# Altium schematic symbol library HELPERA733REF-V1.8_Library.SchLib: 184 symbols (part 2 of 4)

## AO4409_5
designator U?
pins: 1 PK14/MCSIB-CKN/PCIE-PERSTN/PWM0-7/NCSI1-D5/PK-EINT14, 2 PK15/MCSIB-CKP/PWM0-8/NCSI1-D4/PK-EINT15, 3 PK16/MCSIB-D2N/TWI3-SCK/UART2-TX/PWM0-9/NCSI1-D3/PK-EINT16, 4 PK17/MCSIB-D2P/TWI3-SDA/UART2-RX/PWM1-0/NCSI1-D2/PK-EINT17, 5 PK18/MCSIB-D3N/MCSI1-MCLK/UART2-RTS/PWM1-1/NCSI1-D1/TWI9-SCK/PK-EINT18, 6 PK19/MCSIB-D3P/MCSI2-MCLK/UART2-CTS/PWM1-2/NCSI1-D0/TWI9-SDA/PK-EINT19, 7 PE3/TWI3-SCK/CSI1-XVS-FSYNC/PWM0-0/SPI3-MISO/LPC-LFRAME/NCSI0-D1/UART6-CTS/PE-EINT3, 8 PE4/TWI3-SDA/LEDC/PWM0-1/SPI3-CS1/LPC-LSMI/NCSI0-D0/UART6-DCD/PE-EINT4, 9 PE5/MCSI1-MCLK/PLL-LOCK-DBG/PWM0-2/LPC-LCLK/NCSI0-MCLK/UART6-DSR/PE-EINT5, 10 PK8/MCSIA-D3N/MCSI0-MCLK/UART4-RTS/UART2-TX/SPI3-CS1/NCSI1-D11/JTAG-MAS-NTRST/PK-EINT8, 11 PK9/MCSIA-D3P/MCSI2-MCLK/UART4-CTS/UART2-RX/NCSI1-D10/JTAG-MAS-SRST/PK-EINT9, 12 PK6/MCSIA-D2N/TWI2-SCK/UART4-TX/UART2-RTS/SPI3-MOSI/NCSI1-D13/JTAG-MAS-DO/PK-EINT6, 13 PK7/MCSIA-D2P/TWI2-SDA/UART4-RX/UART2-CTS/SPI3-MISO/NCSI1-D12/JTAG-MAS-DI/PK-EINT7, 14 PK2/MCSIA-D1N/UART6-DTR/I2S4-LRCK/HDMI-SDA/TWI5-SDA/NCSI1-PCLK/SGPIO-SDATAIN/PK-EINT2, 15 PK3/MCSIA-D1P/UART6-RI/I2S4-DIN0/I2S4-DOUT1/TWI5-SCK/NCSI1-MCLK/SGPIO-SDATAOUT/PK-EINT3, 16 PK0/MCSIA-D0N/UART6-DCD/I2S4-BCLK/HDMI-CEC/TWI1-SDA/NCSI1-HSYNC/SGPIO-SLOAD/PK-EINT0, 17 PK1/MCSIA-D0P/UART6-DSR/I2S4-MCLK/HDMI-SCL/TWI1-SCK/NCSI1-VSYNC/SGPIO-SCLK/PK-EINT1, 18 PK4/MCSIA-CKN/PCIE-WAKEN/I2S4-DOUT0/I2S4-DIN1/SPI3-CS0/NCSI1-D15/JTAG-MAS-MS/PK-EINT4, 19 PK5/MCSIA-CKP/PCIE-CLKREQN/PWM1-8/PWM1-9/SPI3-CLK/NCSI1-D14/JTAG-MAS-CK/PK-EINT5, 20 PK22/MCSIC-D1N/TWI3-SCK/UART3-RTS/PWM1-6/NCSI1-HSYNC/UART1-TX/PK-EINT22, 21 PK23/MCSIC-D1P/TWI3-SDA/UART3-CTS/PWM1-7/NCSI1-VSYNC/UART1-RX/PK-EINT23, 22 PK20/MCSIC-D0N/TWI2-SCK/UART3-TX/PWM0-1/NCSI1-PCLK/UART1-RTS/PK-EINT20, 23 PK21/MCSIC-D0P/TWI2-SDA/UART3-RX/PWM0-2/NCSI1-MCLK/UART1-CTS/PK-EINT21, 24 PK24/MCSIC-CKN/MCSI0-MCLK/PWM0-6/TWI12-SCK/TWI10-SDA/PK-EINT24, 25 PK25/MCSIC-CKP/MCSI1-MCLK/PWM0-7/TWI12-SDA/TWI10-SCK/PK-EINT25, 26 PE0/MCSI0-MCLK/CSI0-XHS/SPI3-CS0/LPC-LAD0/NCSI0-HSYNC/UART6-TX/PE-EINT0, 27 PE9/MCSI2-MCLK/TCON-FSYNC0/I2S3-MCLK/LPC-LRESET/NCSI0-D5/UART6-RI/PE-EINT9, 28 PE6/CLK-FANOUT1/HDMI-CEC/I2S3-DIN0/I2S3-DOUT1/LPC-SERIRQ/NCSI0-D2/UART6-DTR/PE-EINT6, 29 PE7/CLK-FANOUT2/HDMI-SCL/I2S3-BCLK/LPC-LAD1/NCSI0-D3/TWI11-SCK/PE-EINT7, 30 PE8/CLK-FANOUT3/HDMI-SDA/I2S3-LRCK/LPC-LAD2/NCSI0-D4/TWI11-SDA/PE-EINT8, 31 PE10/TWI4-SCK/TCON-FSYNC1/I2S3-DIN3/I2S3-DOUT3/LPC-LAD3/NCSI0-D6/UART1-RTS/PE-EINT10, 32 PE1/TWI2-SCK/CSI1-XHS/SPI3-CLK/LPC-LPME/NCSI0-VSYNC/UART6-RX/PE-EINT1, 33 PE2/TWI2-SDA/CSI0-XVS-FSYNC/SPI3-MOSI/LPC-LPCPD/NCSI0-PCLK/UART6-RTS/PE-EINT2, 34 AFVCC-CSI, 35 DVDD-CSI, 36 AVDD-CSI, 37 IOVDD-CSI, 38 GND, 39 HCEC, 40 HHPD, 41 HSDA, 42 HSCL, 43 HTXCN, 44 HTXCP, 45 HTX0N, 46 HTX0P, 47 HTX1N, 48 HTX1P, 49 HTX2N, 50 HTX2P, 51 PD0/LCD0-D2/LVDS0-D0P/DSI0-D0P/EINK-D0/PWM0-0/PD-EINT0, 52 PD1/LCD0-D3/LVDS0-D0N/DSI0-D0N/EINK-D1/PWM0-1/PD-EINT1, 53 PD2/LCD0-D4/LVDS0-D1P/DSI0-D1P/EINK-D2/PWM0-2/PD-EINT2, 54 PD3/LCD0-D5/LVDS0-D1N/DSI0-D1N/EINK-D3/PWM0-3/PD-EINT3, 55 PD4/LCD0-D6/LVDS0-D2P/DSI0-CKP/EINK-D4/PWM0-4/PD-EINT4, 56 PD5/LCD0-D7/LVDS0-D2N/DSI0-CKN/EINK-D5/PWM0-5/PD-EINT5, 57 PD6/LCD0-D10/LVDS0-CKP/DSI0-D2P/EINK-D6/PWM0-6/PD-EINT6, 58 PD7/LCD0-D11/LVDS0-CKN/DSI0-D2N/EINK-D7/PWM0-7/PD-EINT7, 59 PD8/LCD0-D12/LVDS0-D3P/DSI0-D3P/EINK-D8/PWM0-8/PD-EINT8, 60 PD9/LCD0-D13/LVDS0-D3N/DSI0-D3N/EINK-D9/PWM0-9/PD-EINT9, 61 PD10/LCD0-D14/LVDS1-D0P/DSI1-D0P/EINK-D10/SPI1-CS0<DBI-CSX>/PWM1-0/PD-EINT10, 62 PD11/LCD0-D15/LVDS1-D0N/DSI1-D0N/EINK-D11/SPI1-CLK<DBI-SCLK>/PWM1-1/PD-EINT11, 63 PD12/LCD0-D18/LVDS1-D1P/DSI1-D1P/EINK-D12/SPI1-MOSI<DBI-SDO>/PWM1-2/PD-EINT12, 64 PD13/LCD0-D19/LVDS1-D1N/DSI1-D1N/EINK-D13/SPI1-MISO<DBI-SDI/DBI-TE/DBI-DCX>/PWM1-3/PD-EINT13, 65 PD14/LCD0-D20/LVDS1-D2P/DSI1-CKP/EINK-D14/SPI1-HOLD<DBI-DCX/DBI-WRX>/UART3-RTS/PD-EINT14, 66 PD15/LCD0-D21/LVDS1-D2N/DSI1-CKN/EINK-D15/SPI1-CS1/UART3-CTS/PD-EINT15, 67 PD16/LCD0-D22/LVDS1-CKP/DSI1-D2P/EINK-OEH/TWI2-SCK/UART3-TX/PD-EINT16, 68 PD17/LCD0-D23/LVDS1-CKN/DSI1-D2N/EINK-LEH/TWI2-SDA/UART3-RX/PD-EINT17, 69 PD18/LCD0-CLK/LVDS1-D3P/DSI1-D3P/EINK-CKH/SPI1-WP<DBI-TE>/UART4-RTS/PD-EINT18, 70 PD19/LCD0-DE/LVDS1-D3N/DSI1-D3N/EINK-STH/PWM1-5/UART4-CTS/PD-EINT19, 71 PF6/PF-EINT6, 72 PF0/SDC0-D1/JTAG-MS/TRACE-DATA3/UART5-RTS/TWI2-SCK/PF-EINT0, 73 PF3/SDC0-D0/JTAG-DI/TRACE-DATA0/UART5-CTS/TWI2-SDA/PF-EINT3, 74 PF2/SDC0-CLK/UART0-TX/TRACE-CLK/PF-EINT2, 75 PF1/SDC0-CMD/JTAG-DO/TRACE-DATA2/PF-EINT1, 76 PF4/SDC0-D3/UART0-RX/UART5-RX/PF-EINT4, 77 PF5/SDC0-D2/JTAG-CK/TRACE-DATA1/UART5-TX/PF-EINT5, 78 PD20/LCD0-HSYNC/DSI-TRIG-LCD-TE1/TWI0-SCK/EINK-CKV /PCIE-CLKREQN/UART4-TX/TWI3-SCK/PWM0-2/PD-EINT20, 79 PD21/LCD0-VSYNC/TWI0-SDA/EINK-MODE/PCIE-WAKEN/UART4-RX/TWI3-SDA/PWM0-3/PD-EINT21, 80 PD22/PWM0-4/EINK-STV/PCIE-PERSTN/TWI0-SCK/TWI2-SCK/PWM1-4/PD-EINT22, 81 PD23/PWM0-5/PCIE-CLKREQN/TWI0-SDA/TWI2-SDA/PWM1-5/PD-EINT23, 82 PH15/UART5-RTS/LEDC/DSI-TRIG-LCD-TE1/RGMII0-EPHY-25/50M/PH-EINT15, 83 PH3/TWI1-SDA/I2S2-BCLK/RGMII0-CLKIN/RMII0-RXER/SPI1-MISO/PH-EINT3, 84 PH12/DMIC-DATA3/SPI2-CS1/RGMII0-RXCK/RMII0-NULL/PH-EINT12, 85 PH2/TWI1-SCK/I2S2-MCLK/RGMII0-RXCTL/RMII0-CRS-DV/SPI1-CS1/PH-EINT2, 86 PH1/TWI0-SDA/I2S2-DOUT3/I2S2-DIN3/RGMII0-RXD0/RMII0-RXD0/TWI3-SDA/SPI1-WP/PH-EINT1, 87 PH0/TWI0-SCK/I2S2-DOUT2/I2S2-DIN2/RGMII0-RXD1/RMII0-RXD1/TWI3-SCK/SPI1-HOLD/PH-EINT0, 88 PH11/DMIC-DATA2/SPI2-MISO/RGMII0-RXD2/RMII0-NULL/PH-EINT11, 89 PH10/DMIC-DATA1/SPI2-MOSI/RGMII0-RXD3/RMII0-NULL/PH-EINT10, 90 PH6/UART3-RTS/I2S2-DOUT1/I2S2-DIN0/RGMII0-TXCK/RMII0-TXCK/SPI1-CLK/PH-EINT6, 91 PH7/UART3-CTS/SPI2-CS2/DSI-TRIG-LCD-TE1/RGMII0-TXCTL/RMII0-TXEN/PH-EINT7, 92 PH5/UART3-RX/I2S2-DIN1/I2S2-DOUT0/RGMII0-TXD0/RMII0-TXD0/SPI1-MOSI/PH-EINT5, 93 PH4/UART3-TX/SPI2-CS3/I2S2-LRCK/RGMII0-TXD1/RMII0-TXD1/SPI1-CS0/PH-EINT4, 94 PH14/UART5-RX/RGMII0-TXD2/RMII0-NULL/TWI7-SCK/PH-EINT14, 95 GND, 96 PH13/UART5-TX/RGMII0-TXD3/RMII0-NULL/TWI7-SDA/PH-EINT13, 97 PH9/DMIC-DATA0/SPI2-CS0/RGMII0-MDIO/PH-EINT9, 98 PH8/DMIC-CLK/SPI2-CLK/RGMII0-MDC/PH-EINT8, 99 PH16/UART5-CTS/IR-TX/PH-EINT16, 100 PJ22/PWM1-4/UART3-TX/UART2-RTS/TWI7-SCK/TWI3-SCK/TWI11-SCK/LCD0-D8/PJ-EINT22, 101 PJ23/PWM1-5/UART3-RX/UART2-CTS/TWI7-SDA/TWI3-SDA/TWI11-SDA/LCD0-D9/PJ-EINT23, 102 PJ24/PWM1-6/UART4-TX/TWI4-SCK/SPI3-CLK/PJ-EINT24, 103 PJ25/PWM1-7/UART4-RX/TWI4-SDA/SPI3-MOSI/PJ-EINT25, 104 PJ26/PWM1-8/UART4-RTS/UART2-TX/TWI5-SCK/SPI3-MISO/LCD0-D16/PJ-EINT26, 105 PJ27/PWM1-9/UART4-CTS/UART2-RX/DSI-TRIG-LCD-TE1/TWI5-SDA/SPI3-CS0/LCD0-D17/PJ-EINT27, 106 PB0/UART2-TX/UART0-TX/SPI2-CS0/DSI-TRIG-LCD-TE1/LCD0-D0/JTAG-MS/PB-EINT0, 107 PB1/UART2-RX/UART0-RX/SPI2-CLK/LCD0-D1/JTAG-CK/PB-EINT1, 108 PB2/UART2-RTS/SPI2-MOSI/HDMI-SCL/LCD0-D8/JTAG-DO/TWI0-SCK/PB-EINT2, 109 PB3/UART2-CTS/SPI2-MISO/HDMI-SDA/LCD0-D9/JTAG-DI/TWI0-SDA/PB-EINT3, 110 PB4/PWM0-0/I2S0-MCLK/SPI2-CS1/HDMI-CEC/LCD0-D16/TRACE-CLK/TWI1-SCK/PB-EINT4, 111 PB5/I2S0-BCLK/SPI2-CS2/PWM0-1/LCD0-D17/TRACE-DATA0/TWI1-SDA/PB-EINT5, 112 PB6/CLK-FANOUT1/I2S0-LRCK/SPI2-CS3/PWM0-2/PWM0-8/TRACE-DATA1/PB-EINT6, 113 PB7/CLK-FANOUT2/I2S0-DOUT0/I2S0-DIN1/PWM0-9/OWA0-IN/TRACE-DATA2/TWI1-SCK/PB-EINT7, 114 PB8/CLK-FANOUT3/I2S0-DIN0/I2S0-DOUT1/PWM1-0/OWA0-OUT/TRACE-DATA3/TWI1-SDA/PB-EINT8, 115 PB9/UART0-TX/I2S0-DIN2/I2S0-DOUT2/PWM1-1/WATCHDOG-SIG/LCD0-D16/TWI8-SCK/TWI0-SCK/PB-EINT9, 116 PB10/UART0-RX/I2S0-DIN3/I2S0-DOUT3/PWM1-2/PLL-LOCK-DBG/LCD0-D17/TWI8-SDA/TWI0-SDA/PB-EINT10, 117 USB0-DM, 118 USB0-DP, 119 USB1-DM, 120 USB1-DP, 121 PCIE1-TX0P/USB2-U3-TX0P, 122 PCIE1-TX0N/USB2-U3-TX0N, 123 USB2-DM, 124 USB2-DP, 125 PCIE1-RX0P/USB2-U3-RX0P, 126 PCIE1-RX0N/USB2-U3-RX0N, 127 COMB1-REF-CLKP, 128 COMB1-REF-CLKN, 129 PE11/TWI4-SDA/SPI3-MISO/I2S3-DIN2/I2S3-DOUT2/PCIE-CLKREQN/NCSI0-D7/UART1-CTS/PE-EINT11, 130 PE13/SPI3-CLK/PCIE-PERSTN/UART1-RX/PE-EINT13, 131 PE14/SPI3-MOSI/PWM1-8/PCIE-CLKREQN/IR-RX/TWI9-SCK/PE-EINT14, 132 PE12/SPI3-CS0/I2S3-DOUT0/I2S3-DIN1/PCIE-WAKEN/UART1-TX/PE-EINT12, 133 PE15/SPI3-CS1/PWM1-9/IR-RX/TWI9-SDA/PE-EINT15, 134 DP-HPD, 135 DP-AUXN, 136 DP-AUXP, 137 TYPEC-TX1P/U3-TX0P/DP/EDP-TX0P, 138 TYPEC-TX1N/U3-TX0N/DP/EDP-TX0N, 139 TYPEC-RX1P/U3-RX0N/DP/EDP-TX1P, 140 TYPEC-RX1N/U3-RX0P/DP/EDP-TX1N, 141 TYPEC-RX2P/U3-RX0P/DP/EDP-TX2P, 142 TYPEC-RX2N/U3-RX0N/DP/EDP-TX2N, 143 TYPEC-TX2P/U3-TX0P/DP/EDP-TX3P, 144 TYPEC-TX2N/U3-TX0N/DP/EDP-TX3N, 145 FEL, 146 PC7/NAND-RB1/SPI0-CS1/SPIF0-DQS/PC-EINT7, 147 PC3/NAND-CE1/SPI0-CS0/SPIF0-CS0/PC-EINT3, 148 PC4/NAND-CE0/SPI0-MISO/SPIF0-MISO/PC-EINT4, 149 PC2/NAND-CLE/SPI0-MOSI/SPIF0-MOSI/PC-EINT2, 150 PC12/NAND-DQS/SPI0-CLK/SPIF0-CLK/PC-EINT12, 151 PC15/NAND-DQ1/SDC2-D2/SDC3-D2/SPI0-WP/SPIF0-WP/PC-EINT15, 152 PC16/NAND-DQ0/SDC2-D7/SDC3-D7/SPI0-HOLD/SPIF0-HOLD/PC-EINT16, 153 PC13/NAND-DQ3/SDC2-D1/SDC3-D1/PC-EINT13, 154 PC14/NAND-DQ2/SDC2-D6/SDC3-D6/PC-EINT14, 155 GPADC4, 156 GPADC5, 157 GPADC6, 158 GND, 159 PMU-IRQ, 160 PMU-SCK, 161 PMU-SDA, 162 GND, 163 5V-IN, 164 5V-IN, 165 GND, 166 BKUPBAT, 167 RESET, 168 PWRON, 169 PM5/S-UART0-RX/S-TWI2-SDA/S-TWI1-SDA/S-UART1-RX/S-PWM0-1/S-IR-RX/PM-EINT5, 170 PL13/S-UART1-RX/S-TWI1-SDA/S-TWI2-SDA/PL-EINT13, 171 PL12/S-UART1-TX/S-TWI1-SCK/S-TWI2-SCK/S-IR-RX/PL-EINT12, 172 PL2/S-UART1-TX/S-UART0-TX/S-TWI1-SDA/S-PWM0-0/PL-EINT2, 173 PL3/S-UART1-RX/S-UART0-RX/S-TWI1-SCK/S-IR-RX/S-PWM0-1/PL-EINT3, 174 PL4/S-JTAG-MS/S-TWI2-SCK/S-SPI0-CS0/S-IR-RX/S-PWM0-2/PL-EINT4, 175 PL5/S-JTAG-CK/S-TWI2-SDA/S-SPI0-CLK/S-PWM0-3/PL-EINT5, 176 PL6/S-JTAG-DO/S-UART0-TX/S-SPI0-MOSI/S-IR-RX/S-PWM0-4/PL-EINT6, 177 PL7/S-JTAG-DI/S-UART0-RX/S-SPI0-MISO/S-PWM0-5/PL-EINT7, 178 PL8/S-TWI1-SCK/S-UART1-TX/S-TWI0-SCK/S-TWI2-SCK/S-PWM0-6/PL-EINT8, 179 PL9/S-TWI1-SDA/S-UART1-RX/S-TWI0-SDA/S-TWI2-SDA/S-PWM0-7/PL-EINT9, 180 PL10/S-UART0-TX/S-TWI2-SCK/S-UART1-TX/S-PWM0-8/PL-EINT10, 181 PL11/S-UART0-RX/S-TWI2-SDA/S-UART1-RX/S-IR-RX/S-PWM0-9/PL-EINT11, 182 AVCC, 183 LRADC0, 184 PK12/MCSIB-D1N/UART6-RTS/PWM0-5/NCSI1-D7/PK-EINT12, 185 PK13/MCSIB-D1P/UART6-CTS/PWM0-6/NCSI1-D6/PK-EINT13, 186 PK10/MCSIB-D0N/UART6-TX/PWM0-3/NCSI1-D9/PK-EINT10, 187 PK11/MCSIB-D0P/UART6-RX/PWM0-4/NCSI1-D8/PK-EINT11, 188 GND, 189 GND, 190 GND

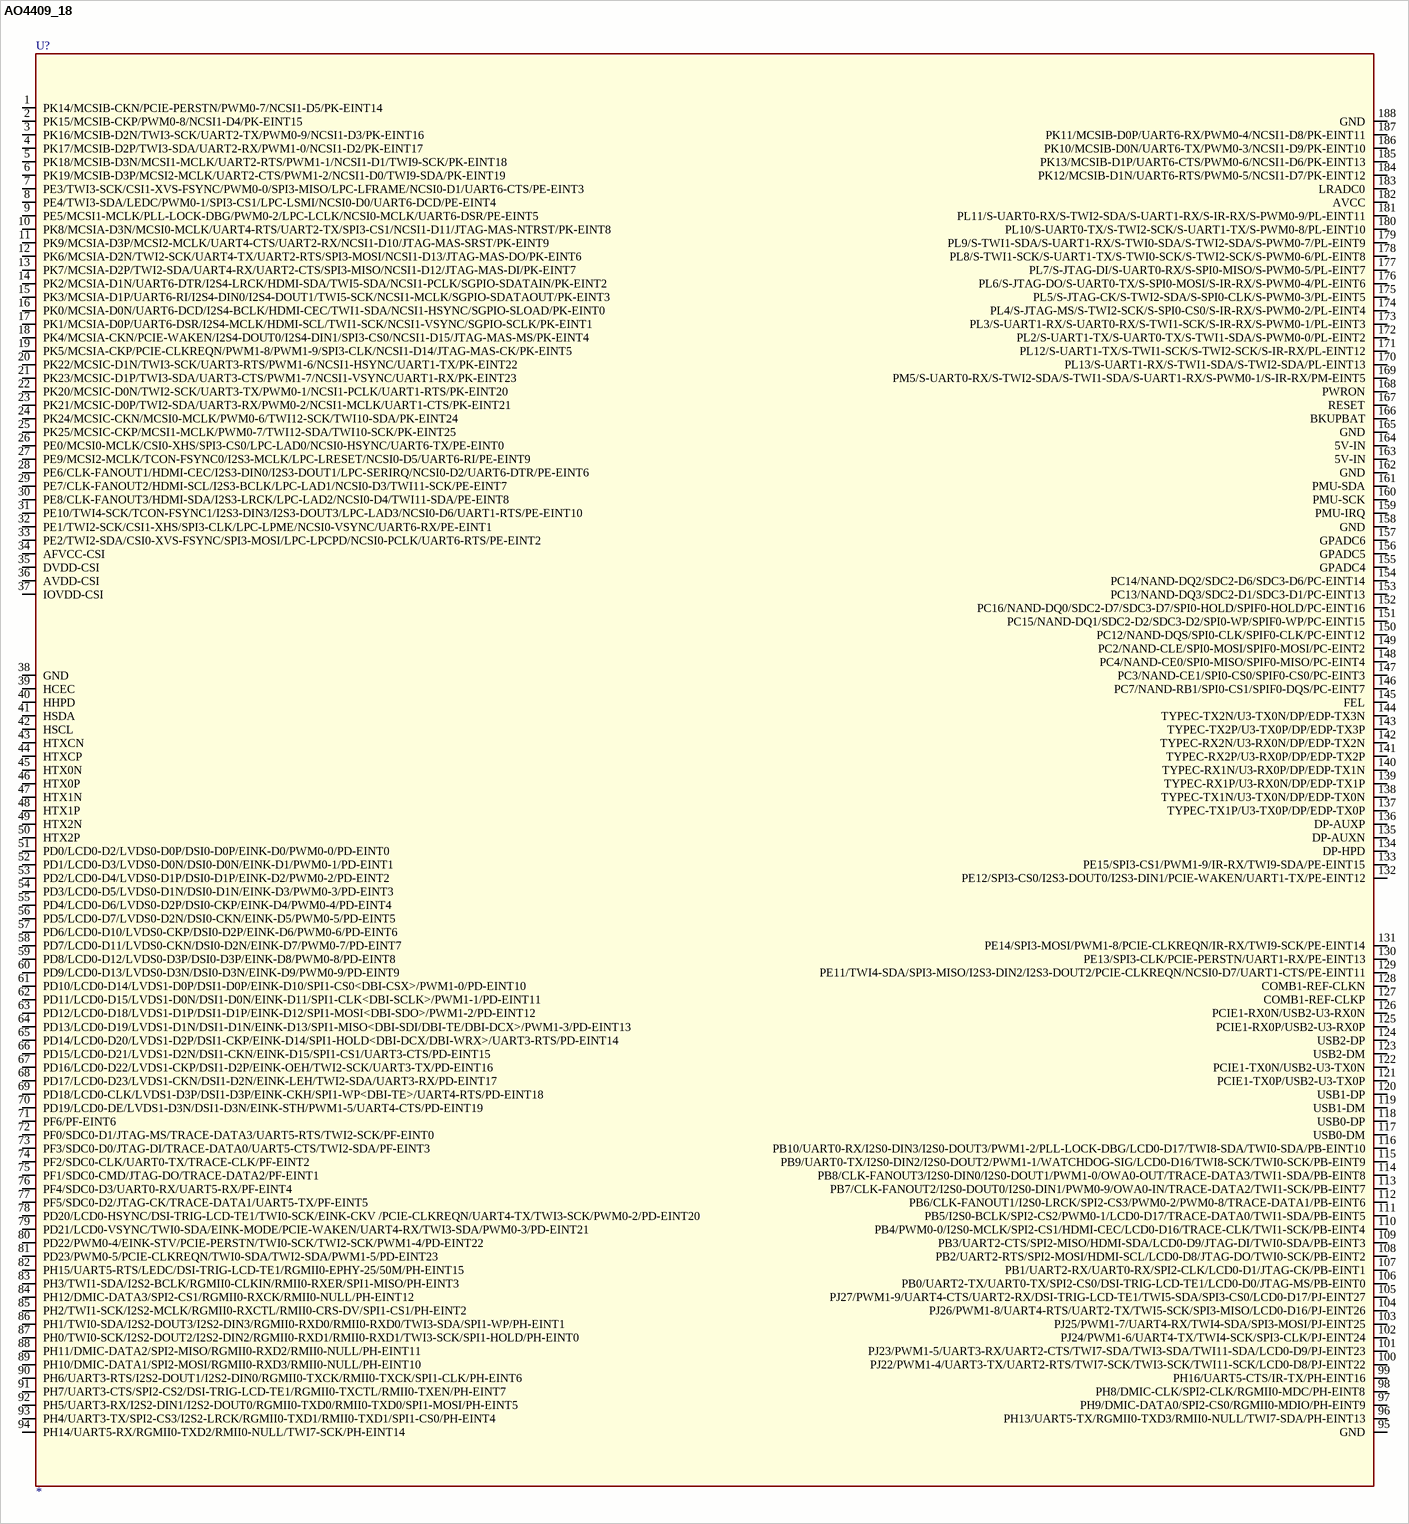
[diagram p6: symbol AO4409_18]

## AO4409_18
designator U?
pins: 1 PK14/MCSIB-CKN/PCIE-PERSTN/PWM0-7/NCSI1-D5/PK-EINT14, 2 PK15/MCSIB-CKP/PWM0-8/NCSI1-D4/PK-EINT15, 3 PK16/MCSIB-D2N/TWI3-SCK/UART2-TX/PWM0-9/NCSI1-D3/PK-EINT16, 4 PK17/MCSIB-D2P/TWI3-SDA/UART2-RX/PWM1-0/NCSI1-D2/PK-EINT17, 5 PK18/MCSIB-D3N/MCSI1-MCLK/UART2-RTS/PWM1-1/NCSI1-D1/TWI9-SCK/PK-EINT18, 6 PK19/MCSIB-D3P/MCSI2-MCLK/UART2-CTS/PWM1-2/NCSI1-D0/TWI9-SDA/PK-EINT19, 7 PE3/TWI3-SCK/CSI1-XVS-FSYNC/PWM0-0/SPI3-MISO/LPC-LFRAME/NCSI0-D1/UART6-CTS/PE-EINT3, 8 PE4/TWI3-SDA/LEDC/PWM0-1/SPI3-CS1/LPC-LSMI/NCSI0-D0/UART6-DCD/PE-EINT4, 9 PE5/MCSI1-MCLK/PLL-LOCK-DBG/PWM0-2/LPC-LCLK/NCSI0-MCLK/UART6-DSR/PE-EINT5, 10 PK8/MCSIA-D3N/MCSI0-MCLK/UART4-RTS/UART2-TX/SPI3-CS1/NCSI1-D11/JTAG-MAS-NTRST/PK-EINT8, 11 PK9/MCSIA-D3P/MCSI2-MCLK/UART4-CTS/UART2-RX/NCSI1-D10/JTAG-MAS-SRST/PK-EINT9, 12 PK6/MCSIA-D2N/TWI2-SCK/UART4-TX/UART2-RTS/SPI3-MOSI/NCSI1-D13/JTAG-MAS-DO/PK-EINT6, 13 PK7/MCSIA-D2P/TWI2-SDA/UART4-RX/UART2-CTS/SPI3-MISO/NCSI1-D12/JTAG-MAS-DI/PK-EINT7, 14 PK2/MCSIA-D1N/UART6-DTR/I2S4-LRCK/HDMI-SDA/TWI5-SDA/NCSI1-PCLK/SGPIO-SDATAIN/PK-EINT2, 15 PK3/MCSIA-D1P/UART6-RI/I2S4-DIN0/I2S4-DOUT1/TWI5-SCK/NCSI1-MCLK/SGPIO-SDATAOUT/PK-EINT3, 16 PK0/MCSIA-D0N/UART6-DCD/I2S4-BCLK/HDMI-CEC/TWI1-SDA/NCSI1-HSYNC/SGPIO-SLOAD/PK-EINT0, 17 PK1/MCSIA-D0P/UART6-DSR/I2S4-MCLK/HDMI-SCL/TWI1-SCK/NCSI1-VSYNC/SGPIO-SCLK/PK-EINT1, 18 PK4/MCSIA-CKN/PCIE-WAKEN/I2S4-DOUT0/I2S4-DIN1/SPI3-CS0/NCSI1-D15/JTAG-MAS-MS/PK-EINT4, 19 PK5/MCSIA-CKP/PCIE-CLKREQN/PWM1-8/PWM1-9/SPI3-CLK/NCSI1-D14/JTAG-MAS-CK/PK-EINT5, 20 PK22/MCSIC-D1N/TWI3-SCK/UART3-RTS/PWM1-6/NCSI1-HSYNC/UART1-TX/PK-EINT22, 21 PK23/MCSIC-D1P/TWI3-SDA/UART3-CTS/PWM1-7/NCSI1-VSYNC/UART1-RX/PK-EINT23, 22 PK20/MCSIC-D0N/TWI2-SCK/UART3-TX/PWM0-1/NCSI1-PCLK/UART1-RTS/PK-EINT20, 23 PK21/MCSIC-D0P/TWI2-SDA/UART3-RX/PWM0-2/NCSI1-MCLK/UART1-CTS/PK-EINT21, 24 PK24/MCSIC-CKN/MCSI0-MCLK/PWM0-6/TWI12-SCK/TWI10-SDA/PK-EINT24, 25 PK25/MCSIC-CKP/MCSI1-MCLK/PWM0-7/TWI12-SDA/TWI10-SCK/PK-EINT25, 26 PE0/MCSI0-MCLK/CSI0-XHS/SPI3-CS0/LPC-LAD0/NCSI0-HSYNC/UART6-TX/PE-EINT0, 27 PE9/MCSI2-MCLK/TCON-FSYNC0/I2S3-MCLK/LPC-LRESET/NCSI0-D5/UART6-RI/PE-EINT9, 28 PE6/CLK-FANOUT1/HDMI-CEC/I2S3-DIN0/I2S3-DOUT1/LPC-SERIRQ/NCSI0-D2/UART6-DTR/PE-EINT6, 29 PE7/CLK-FANOUT2/HDMI-SCL/I2S3-BCLK/LPC-LAD1/NCSI0-D3/TWI11-SCK/PE-EINT7, 30 PE8/CLK-FANOUT3/HDMI-SDA/I2S3-LRCK/LPC-LAD2/NCSI0-D4/TWI11-SDA/PE-EINT8, 31 PE10/TWI4-SCK/TCON-FSYNC1/I2S3-DIN3/I2S3-DOUT3/LPC-LAD3/NCSI0-D6/UART1-RTS/PE-EINT10, 32 PE1/TWI2-SCK/CSI1-XHS/SPI3-CLK/LPC-LPME/NCSI0-VSYNC/UART6-RX/PE-EINT1, 33 PE2/TWI2-SDA/CSI0-XVS-FSYNC/SPI3-MOSI/LPC-LPCPD/NCSI0-PCLK/UART6-RTS/PE-EINT2, 34 AFVCC-CSI, 35 DVDD-CSI, 36 AVDD-CSI, 37 IOVDD-CSI, 38 GND, 39 HCEC, 40 HHPD, 41 HSDA, 42 HSCL, 43 HTXCN, 44 HTXCP, 45 HTX0N, 46 HTX0P, 47 HTX1N, 48 HTX1P, 49 HTX2N, 50 HTX2P, 51 PD0/LCD0-D2/LVDS0-D0P/DSI0-D0P/EINK-D0/PWM0-0/PD-EINT0, 52 PD1/LCD0-D3/LVDS0-D0N/DSI0-D0N/EINK-D1/PWM0-1/PD-EINT1, 53 PD2/LCD0-D4/LVDS0-D1P/DSI0-D1P/EINK-D2/PWM0-2/PD-EINT2, 54 PD3/LCD0-D5/LVDS0-D1N/DSI0-D1N/EINK-D3/PWM0-3/PD-EINT3, 55 PD4/LCD0-D6/LVDS0-D2P/DSI0-CKP/EINK-D4/PWM0-4/PD-EINT4, 56 PD5/LCD0-D7/LVDS0-D2N/DSI0-CKN/EINK-D5/PWM0-5/PD-EINT5, 57 PD6/LCD0-D10/LVDS0-CKP/DSI0-D2P/EINK-D6/PWM0-6/PD-EINT6, 58 PD7/LCD0-D11/LVDS0-CKN/DSI0-D2N/EINK-D7/PWM0-7/PD-EINT7, 59 PD8/LCD0-D12/LVDS0-D3P/DSI0-D3P/EINK-D8/PWM0-8/PD-EINT8, 60 PD9/LCD0-D13/LVDS0-D3N/DSI0-D3N/EINK-D9/PWM0-9/PD-EINT9, 61 PD10/LCD0-D14/LVDS1-D0P/DSI1-D0P/EINK-D10/SPI1-CS0<DBI-CSX>/PWM1-0/PD-EINT10, 62 PD11/LCD0-D15/LVDS1-D0N/DSI1-D0N/EINK-D11/SPI1-CLK<DBI-SCLK>/PWM1-1/PD-EINT11, 63 PD12/LCD0-D18/LVDS1-D1P/DSI1-D1P/EINK-D12/SPI1-MOSI<DBI-SDO>/PWM1-2/PD-EINT12, 64 PD13/LCD0-D19/LVDS1-D1N/DSI1-D1N/EINK-D13/SPI1-MISO<DBI-SDI/DBI-TE/DBI-DCX>/PWM1-3/PD-EINT13, 65 PD14/LCD0-D20/LVDS1-D2P/DSI1-CKP/EINK-D14/SPI1-HOLD<DBI-DCX/DBI-WRX>/UART3-RTS/PD-EINT14, 66 PD15/LCD0-D21/LVDS1-D2N/DSI1-CKN/EINK-D15/SPI1-CS1/UART3-CTS/PD-EINT15, 67 PD16/LCD0-D22/LVDS1-CKP/DSI1-D2P/EINK-OEH/TWI2-SCK/UART3-TX/PD-EINT16, 68 PD17/LCD0-D23/LVDS1-CKN/DSI1-D2N/EINK-LEH/TWI2-SDA/UART3-RX/PD-EINT17, 69 PD18/LCD0-CLK/LVDS1-D3P/DSI1-D3P/EINK-CKH/SPI1-WP<DBI-TE>/UART4-RTS/PD-EINT18, 70 PD19/LCD0-DE/LVDS1-D3N/DSI1-D3N/EINK-STH/PWM1-5/UART4-CTS/PD-EINT19, 71 PF6/PF-EINT6, 72 PF0/SDC0-D1/JTAG-MS/TRACE-DATA3/UART5-RTS/TWI2-SCK/PF-EINT0, 73 PF3/SDC0-D0/JTAG-DI/TRACE-DATA0/UART5-CTS/TWI2-SDA/PF-EINT3, 74 PF2/SDC0-CLK/UART0-TX/TRACE-CLK/PF-EINT2, 75 PF1/SDC0-CMD/JTAG-DO/TRACE-DATA2/PF-EINT1, 76 PF4/SDC0-D3/UART0-RX/UART5-RX/PF-EINT4, 77 PF5/SDC0-D2/JTAG-CK/TRACE-DATA1/UART5-TX/PF-EINT5, 78 PD20/LCD0-HSYNC/DSI-TRIG-LCD-TE1/TWI0-SCK/EINK-CKV /PCIE-CLKREQN/UART4-TX/TWI3-SCK/PWM0-2/PD-EINT20, 79 PD21/LCD0-VSYNC/TWI0-SDA/EINK-MODE/PCIE-WAKEN/UART4-RX/TWI3-SDA/PWM0-3/PD-EINT21, 80 PD22/PWM0-4/EINK-STV/PCIE-PERSTN/TWI0-SCK/TWI2-SCK/PWM1-4/PD-EINT22, 81 PD23/PWM0-5/PCIE-CLKREQN/TWI0-SDA/TWI2-SDA/PWM1-5/PD-EINT23, 82 PH15/UART5-RTS/LEDC/DSI-TRIG-LCD-TE1/RGMII0-EPHY-25/50M/PH-EINT15, 83 PH3/TWI1-SDA/I2S2-BCLK/RGMII0-CLKIN/RMII0-RXER/SPI1-MISO/PH-EINT3, 84 PH12/DMIC-DATA3/SPI2-CS1/RGMII0-RXCK/RMII0-NULL/PH-EINT12, 85 PH2/TWI1-SCK/I2S2-MCLK/RGMII0-RXCTL/RMII0-CRS-DV/SPI1-CS1/PH-EINT2, 86 PH1/TWI0-SDA/I2S2-DOUT3/I2S2-DIN3/RGMII0-RXD0/RMII0-RXD0/TWI3-SDA/SPI1-WP/PH-EINT1, 87 PH0/TWI0-SCK/I2S2-DOUT2/I2S2-DIN2/RGMII0-RXD1/RMII0-RXD1/TWI3-SCK/SPI1-HOLD/PH-EINT0, 88 PH11/DMIC-DATA2/SPI2-MISO/RGMII0-RXD2/RMII0-NULL/PH-EINT11, 89 PH10/DMIC-DATA1/SPI2-MOSI/RGMII0-RXD3/RMII0-NULL/PH-EINT10, 90 PH6/UART3-RTS/I2S2-DOUT1/I2S2-DIN0/RGMII0-TXCK/RMII0-TXCK/SPI1-CLK/PH-EINT6, 91 PH7/UART3-CTS/SPI2-CS2/DSI-TRIG-LCD-TE1/RGMII0-TXCTL/RMII0-TXEN/PH-EINT7, 92 PH5/UART3-RX/I2S2-DIN1/I2S2-DOUT0/RGMII0-TXD0/RMII0-TXD0/SPI1-MOSI/PH-EINT5, 93 PH4/UART3-TX/SPI2-CS3/I2S2-LRCK/RGMII0-TXD1/RMII0-TXD1/SPI1-CS0/PH-EINT4, 94 PH14/UART5-RX/RGMII0-TXD2/RMII0-NULL/TWI7-SCK/PH-EINT14, 95 GND, 96 PH13/UART5-TX/RGMII0-TXD3/RMII0-NULL/TWI7-SDA/PH-EINT13, 97 PH9/DMIC-DATA0/SPI2-CS0/RGMII0-MDIO/PH-EINT9, 98 PH8/DMIC-CLK/SPI2-CLK/RGMII0-MDC/PH-EINT8, 99 PH16/UART5-CTS/IR-TX/PH-EINT16, 100 PJ22/PWM1-4/UART3-TX/UART2-RTS/TWI7-SCK/TWI3-SCK/TWI11-SCK/LCD0-D8/PJ-EINT22, 101 PJ23/PWM1-5/UART3-RX/UART2-CTS/TWI7-SDA/TWI3-SDA/TWI11-SDA/LCD0-D9/PJ-EINT23, 102 PJ24/PWM1-6/UART4-TX/TWI4-SCK/SPI3-CLK/PJ-EINT24, 103 PJ25/PWM1-7/UART4-RX/TWI4-SDA/SPI3-MOSI/PJ-EINT25, 104 PJ26/PWM1-8/UART4-RTS/UART2-TX/TWI5-SCK/SPI3-MISO/LCD0-D16/PJ-EINT26, 105 PJ27/PWM1-9/UART4-CTS/UART2-RX/DSI-TRIG-LCD-TE1/TWI5-SDA/SPI3-CS0/LCD0-D17/PJ-EINT27, 106 PB0/UART2-TX/UART0-TX/SPI2-CS0/DSI-TRIG-LCD-TE1/LCD0-D0/JTAG-MS/PB-EINT0, 107 PB1/UART2-RX/UART0-RX/SPI2-CLK/LCD0-D1/JTAG-CK/PB-EINT1, 108 PB2/UART2-RTS/SPI2-MOSI/HDMI-SCL/LCD0-D8/JTAG-DO/TWI0-SCK/PB-EINT2, 109 PB3/UART2-CTS/SPI2-MISO/HDMI-SDA/LCD0-D9/JTAG-DI/TWI0-SDA/PB-EINT3, 110 PB4/PWM0-0/I2S0-MCLK/SPI2-CS1/HDMI-CEC/LCD0-D16/TRACE-CLK/TWI1-SCK/PB-EINT4, 111 PB5/I2S0-BCLK/SPI2-CS2/PWM0-1/LCD0-D17/TRACE-DATA0/TWI1-SDA/PB-EINT5, 112 PB6/CLK-FANOUT1/I2S0-LRCK/SPI2-CS3/PWM0-2/PWM0-8/TRACE-DATA1/PB-EINT6, 113 PB7/CLK-FANOUT2/I2S0-DOUT0/I2S0-DIN1/PWM0-9/OWA0-IN/TRACE-DATA2/TWI1-SCK/PB-EINT7, 114 PB8/CLK-FANOUT3/I2S0-DIN0/I2S0-DOUT1/PWM1-0/OWA0-OUT/TRACE-DATA3/TWI1-SDA/PB-EINT8, 115 PB9/UART0-TX/I2S0-DIN2/I2S0-DOUT2/PWM1-1/WATCHDOG-SIG/LCD0-D16/TWI8-SCK/TWI0-SCK/PB-EINT9, 116 PB10/UART0-RX/I2S0-DIN3/I2S0-DOUT3/PWM1-2/PLL-LOCK-DBG/LCD0-D17/TWI8-SDA/TWI0-SDA/PB-EINT10, 117 USB0-DM, 118 USB0-DP, 119 USB1-DM, 120 USB1-DP, 121 PCIE1-TX0P/USB2-U3-TX0P, 122 PCIE1-TX0N/USB2-U3-TX0N, 123 USB2-DM, 124 USB2-DP, 125 PCIE1-RX0P/USB2-U3-RX0P, 126 PCIE1-RX0N/USB2-U3-RX0N, 127 COMB1-REF-CLKP, 128 COMB1-REF-CLKN, 129 PE11/TWI4-SDA/SPI3-MISO/I2S3-DIN2/I2S3-DOUT2/PCIE-CLKREQN/NCSI0-D7/UART1-CTS/PE-EINT11, 130 PE13/SPI3-CLK/PCIE-PERSTN/UART1-RX/PE-EINT13, 131 PE14/SPI3-MOSI/PWM1-8/PCIE-CLKREQN/IR-RX/TWI9-SCK/PE-EINT14, 132 PE12/SPI3-CS0/I2S3-DOUT0/I2S3-DIN1/PCIE-WAKEN/UART1-TX/PE-EINT12, 133 PE15/SPI3-CS1/PWM1-9/IR-RX/TWI9-SDA/PE-EINT15, 134 DP-HPD, 135 DP-AUXN, 136 DP-AUXP, 137 TYPEC-TX1P/U3-TX0P/DP/EDP-TX0P, 138 TYPEC-TX1N/U3-TX0N/DP/EDP-TX0N, 139 TYPEC-RX1P/U3-RX0N/DP/EDP-TX1P, 140 TYPEC-RX1N/U3-RX0P/DP/EDP-TX1N, 141 TYPEC-RX2P/U3-RX0P/DP/EDP-TX2P, 142 TYPEC-RX2N/U3-RX0N/DP/EDP-TX2N, 143 TYPEC-TX2P/U3-TX0P/DP/EDP-TX3P, 144 TYPEC-TX2N/U3-TX0N/DP/EDP-TX3N, 145 FEL, 146 PC7/NAND-RB1/SPI0-CS1/SPIF0-DQS/PC-EINT7, 147 PC3/NAND-CE1/SPI0-CS0/SPIF0-CS0/PC-EINT3, 148 PC4/NAND-CE0/SPI0-MISO/SPIF0-MISO/PC-EINT4, 149 PC2/NAND-CLE/SPI0-MOSI/SPIF0-MOSI/PC-EINT2, 150 PC12/NAND-DQS/SPI0-CLK/SPIF0-CLK/PC-EINT12, 151 PC15/NAND-DQ1/SDC2-D2/SDC3-D2/SPI0-WP/SPIF0-WP/PC-EINT15, 152 PC16/NAND-DQ0/SDC2-D7/SDC3-D7/SPI0-HOLD/SPIF0-HOLD/PC-EINT16, 153 PC13/NAND-DQ3/SDC2-D1/SDC3-D1/PC-EINT13, 154 PC14/NAND-DQ2/SDC2-D6/SDC3-D6/PC-EINT14, 155 GPADC4, 156 GPADC5, 157 GPADC6, 158 GND, 159 PMU-IRQ, 160 PMU-SCK, 161 PMU-SDA, 162 GND, 163 5V-IN, 164 5V-IN, 165 GND, 166 BKUPBAT, 167 RESET, 168 PWRON, 169 PM5/S-UART0-RX/S-TWI2-SDA/S-TWI1-SDA/S-UART1-RX/S-PWM0-1/S-IR-RX/PM-EINT5, 170 PL13/S-UART1-RX/S-TWI1-SDA/S-TWI2-SDA/PL-EINT13, 171 PL12/S-UART1-TX/S-TWI1-SCK/S-TWI2-SCK/S-IR-RX/PL-EINT12, 172 PL2/S-UART1-TX/S-UART0-TX/S-TWI1-SDA/S-PWM0-0/PL-EINT2, 173 PL3/S-UART1-RX/S-UART0-RX/S-TWI1-SCK/S-IR-RX/S-PWM0-1/PL-EINT3, 174 PL4/S-JTAG-MS/S-TWI2-SCK/S-SPI0-CS0/S-IR-RX/S-PWM0-2/PL-EINT4, 175 PL5/S-JTAG-CK/S-TWI2-SDA/S-SPI0-CLK/S-PWM0-3/PL-EINT5, 176 PL6/S-JTAG-DO/S-UART0-TX/S-SPI0-MOSI/S-IR-RX/S-PWM0-4/PL-EINT6, 177 PL7/S-JTAG-DI/S-UART0-RX/S-SPI0-MISO/S-PWM0-5/PL-EINT7, 178 PL8/S-TWI1-SCK/S-UART1-TX/S-TWI0-SCK/S-TWI2-SCK/S-PWM0-6/PL-EINT8, 179 PL9/S-TWI1-SDA/S-UART1-RX/S-TWI0-SDA/S-TWI2-SDA/S-PWM0-7/PL-EINT9, 180 PL10/S-UART0-TX/S-TWI2-SCK/S-UART1-TX/S-PWM0-8/PL-EINT10, 181 PL11/S-UART0-RX/S-TWI2-SDA/S-UART1-RX/S-IR-RX/S-PWM0-9/PL-EINT11, 182 AVCC, 183 LRADC0, 184 PK12/MCSIB-D1N/UART6-RTS/PWM0-5/NCSI1-D7/PK-EINT12, 185 PK13/MCSIB-D1P/UART6-CTS/PWM0-6/NCSI1-D6/PK-EINT13, 186 PK10/MCSIB-D0N/UART6-TX/PWM0-3/NCSI1-D9/PK-EINT10, 187 PK11/MCSIB-D0P/UART6-RX/PWM0-4/NCSI1-D8/PK-EINT11, 188 GND

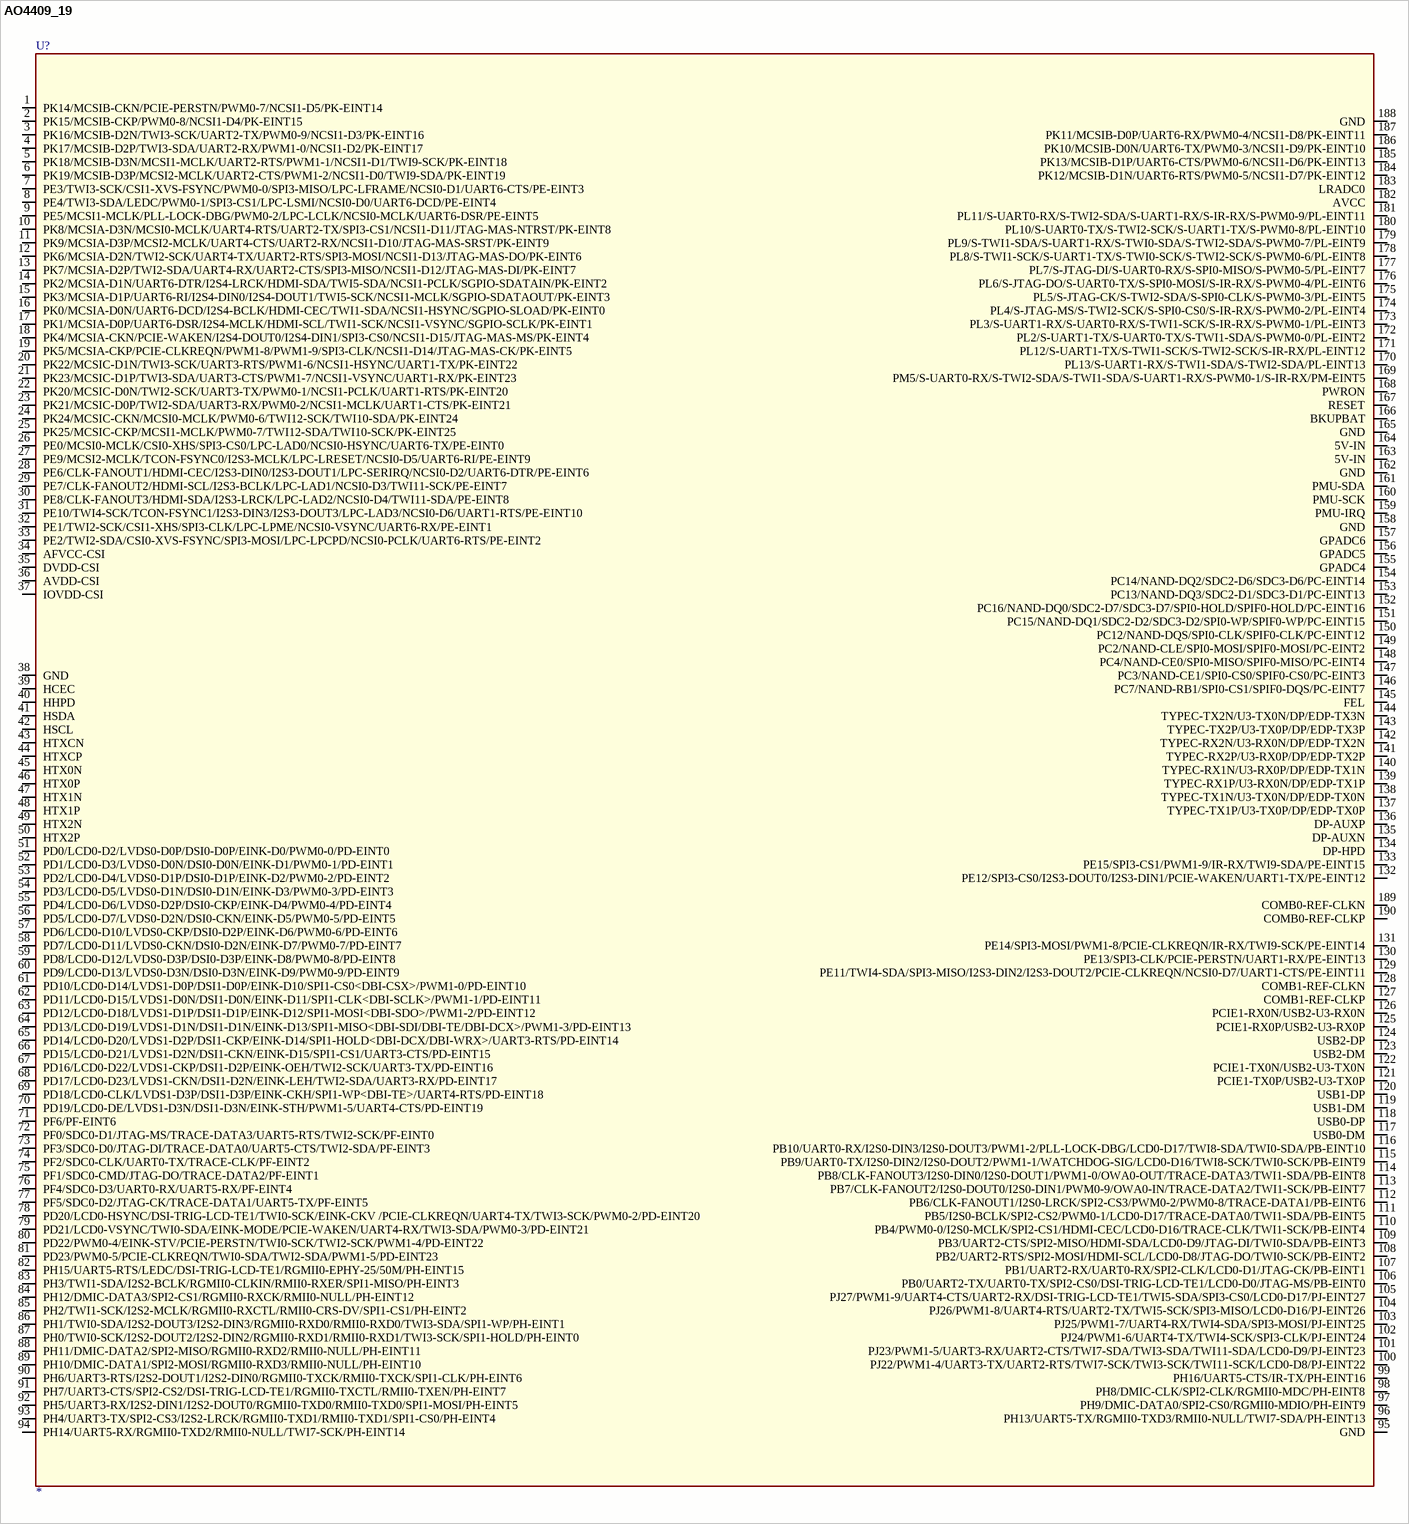
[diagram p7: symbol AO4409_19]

## AO4409_19
designator U?
pins: 1 PK14/MCSIB-CKN/PCIE-PERSTN/PWM0-7/NCSI1-D5/PK-EINT14, 2 PK15/MCSIB-CKP/PWM0-8/NCSI1-D4/PK-EINT15, 3 PK16/MCSIB-D2N/TWI3-SCK/UART2-TX/PWM0-9/NCSI1-D3/PK-EINT16, 4 PK17/MCSIB-D2P/TWI3-SDA/UART2-RX/PWM1-0/NCSI1-D2/PK-EINT17, 5 PK18/MCSIB-D3N/MCSI1-MCLK/UART2-RTS/PWM1-1/NCSI1-D1/TWI9-SCK/PK-EINT18, 6 PK19/MCSIB-D3P/MCSI2-MCLK/UART2-CTS/PWM1-2/NCSI1-D0/TWI9-SDA/PK-EINT19, 7 PE3/TWI3-SCK/CSI1-XVS-FSYNC/PWM0-0/SPI3-MISO/LPC-LFRAME/NCSI0-D1/UART6-CTS/PE-EINT3, 8 PE4/TWI3-SDA/LEDC/PWM0-1/SPI3-CS1/LPC-LSMI/NCSI0-D0/UART6-DCD/PE-EINT4, 9 PE5/MCSI1-MCLK/PLL-LOCK-DBG/PWM0-2/LPC-LCLK/NCSI0-MCLK/UART6-DSR/PE-EINT5, 10 PK8/MCSIA-D3N/MCSI0-MCLK/UART4-RTS/UART2-TX/SPI3-CS1/NCSI1-D11/JTAG-MAS-NTRST/PK-EINT8, 11 PK9/MCSIA-D3P/MCSI2-MCLK/UART4-CTS/UART2-RX/NCSI1-D10/JTAG-MAS-SRST/PK-EINT9, 12 PK6/MCSIA-D2N/TWI2-SCK/UART4-TX/UART2-RTS/SPI3-MOSI/NCSI1-D13/JTAG-MAS-DO/PK-EINT6, 13 PK7/MCSIA-D2P/TWI2-SDA/UART4-RX/UART2-CTS/SPI3-MISO/NCSI1-D12/JTAG-MAS-DI/PK-EINT7, 14 PK2/MCSIA-D1N/UART6-DTR/I2S4-LRCK/HDMI-SDA/TWI5-SDA/NCSI1-PCLK/SGPIO-SDATAIN/PK-EINT2, 15 PK3/MCSIA-D1P/UART6-RI/I2S4-DIN0/I2S4-DOUT1/TWI5-SCK/NCSI1-MCLK/SGPIO-SDATAOUT/PK-EINT3, 16 PK0/MCSIA-D0N/UART6-DCD/I2S4-BCLK/HDMI-CEC/TWI1-SDA/NCSI1-HSYNC/SGPIO-SLOAD/PK-EINT0, 17 PK1/MCSIA-D0P/UART6-DSR/I2S4-MCLK/HDMI-SCL/TWI1-SCK/NCSI1-VSYNC/SGPIO-SCLK/PK-EINT1, 18 PK4/MCSIA-CKN/PCIE-WAKEN/I2S4-DOUT0/I2S4-DIN1/SPI3-CS0/NCSI1-D15/JTAG-MAS-MS/PK-EINT4, 19 PK5/MCSIA-CKP/PCIE-CLKREQN/PWM1-8/PWM1-9/SPI3-CLK/NCSI1-D14/JTAG-MAS-CK/PK-EINT5, 20 PK22/MCSIC-D1N/TWI3-SCK/UART3-RTS/PWM1-6/NCSI1-HSYNC/UART1-TX/PK-EINT22, 21 PK23/MCSIC-D1P/TWI3-SDA/UART3-CTS/PWM1-7/NCSI1-VSYNC/UART1-RX/PK-EINT23, 22 PK20/MCSIC-D0N/TWI2-SCK/UART3-TX/PWM0-1/NCSI1-PCLK/UART1-RTS/PK-EINT20, 23 PK21/MCSIC-D0P/TWI2-SDA/UART3-RX/PWM0-2/NCSI1-MCLK/UART1-CTS/PK-EINT21, 24 PK24/MCSIC-CKN/MCSI0-MCLK/PWM0-6/TWI12-SCK/TWI10-SDA/PK-EINT24, 25 PK25/MCSIC-CKP/MCSI1-MCLK/PWM0-7/TWI12-SDA/TWI10-SCK/PK-EINT25, 26 PE0/MCSI0-MCLK/CSI0-XHS/SPI3-CS0/LPC-LAD0/NCSI0-HSYNC/UART6-TX/PE-EINT0, 27 PE9/MCSI2-MCLK/TCON-FSYNC0/I2S3-MCLK/LPC-LRESET/NCSI0-D5/UART6-RI/PE-EINT9, 28 PE6/CLK-FANOUT1/HDMI-CEC/I2S3-DIN0/I2S3-DOUT1/LPC-SERIRQ/NCSI0-D2/UART6-DTR/PE-EINT6, 29 PE7/CLK-FANOUT2/HDMI-SCL/I2S3-BCLK/LPC-LAD1/NCSI0-D3/TWI11-SCK/PE-EINT7, 30 PE8/CLK-FANOUT3/HDMI-SDA/I2S3-LRCK/LPC-LAD2/NCSI0-D4/TWI11-SDA/PE-EINT8, 31 PE10/TWI4-SCK/TCON-FSYNC1/I2S3-DIN3/I2S3-DOUT3/LPC-LAD3/NCSI0-D6/UART1-RTS/PE-EINT10, 32 PE1/TWI2-SCK/CSI1-XHS/SPI3-CLK/LPC-LPME/NCSI0-VSYNC/UART6-RX/PE-EINT1, 33 PE2/TWI2-SDA/CSI0-XVS-FSYNC/SPI3-MOSI/LPC-LPCPD/NCSI0-PCLK/UART6-RTS/PE-EINT2, 34 AFVCC-CSI, 35 DVDD-CSI, 36 AVDD-CSI, 37 IOVDD-CSI, 38 GND, 39 HCEC, 40 HHPD, 41 HSDA, 42 HSCL, 43 HTXCN, 44 HTXCP, 45 HTX0N, 46 HTX0P, 47 HTX1N, 48 HTX1P, 49 HTX2N, 50 HTX2P, 51 PD0/LCD0-D2/LVDS0-D0P/DSI0-D0P/EINK-D0/PWM0-0/PD-EINT0, 52 PD1/LCD0-D3/LVDS0-D0N/DSI0-D0N/EINK-D1/PWM0-1/PD-EINT1, 53 PD2/LCD0-D4/LVDS0-D1P/DSI0-D1P/EINK-D2/PWM0-2/PD-EINT2, 54 PD3/LCD0-D5/LVDS0-D1N/DSI0-D1N/EINK-D3/PWM0-3/PD-EINT3, 55 PD4/LCD0-D6/LVDS0-D2P/DSI0-CKP/EINK-D4/PWM0-4/PD-EINT4, 56 PD5/LCD0-D7/LVDS0-D2N/DSI0-CKN/EINK-D5/PWM0-5/PD-EINT5, 57 PD6/LCD0-D10/LVDS0-CKP/DSI0-D2P/EINK-D6/PWM0-6/PD-EINT6, 58 PD7/LCD0-D11/LVDS0-CKN/DSI0-D2N/EINK-D7/PWM0-7/PD-EINT7, 59 PD8/LCD0-D12/LVDS0-D3P/DSI0-D3P/EINK-D8/PWM0-8/PD-EINT8, 60 PD9/LCD0-D13/LVDS0-D3N/DSI0-D3N/EINK-D9/PWM0-9/PD-EINT9, 61 PD10/LCD0-D14/LVDS1-D0P/DSI1-D0P/EINK-D10/SPI1-CS0<DBI-CSX>/PWM1-0/PD-EINT10, 62 PD11/LCD0-D15/LVDS1-D0N/DSI1-D0N/EINK-D11/SPI1-CLK<DBI-SCLK>/PWM1-1/PD-EINT11, 63 PD12/LCD0-D18/LVDS1-D1P/DSI1-D1P/EINK-D12/SPI1-MOSI<DBI-SDO>/PWM1-2/PD-EINT12, 64 PD13/LCD0-D19/LVDS1-D1N/DSI1-D1N/EINK-D13/SPI1-MISO<DBI-SDI/DBI-TE/DBI-DCX>/PWM1-3/PD-EINT13, 65 PD14/LCD0-D20/LVDS1-D2P/DSI1-CKP/EINK-D14/SPI1-HOLD<DBI-DCX/DBI-WRX>/UART3-RTS/PD-EINT14, 66 PD15/LCD0-D21/LVDS1-D2N/DSI1-CKN/EINK-D15/SPI1-CS1/UART3-CTS/PD-EINT15, 67 PD16/LCD0-D22/LVDS1-CKP/DSI1-D2P/EINK-OEH/TWI2-SCK/UART3-TX/PD-EINT16, 68 PD17/LCD0-D23/LVDS1-CKN/DSI1-D2N/EINK-LEH/TWI2-SDA/UART3-RX/PD-EINT17, 69 PD18/LCD0-CLK/LVDS1-D3P/DSI1-D3P/EINK-CKH/SPI1-WP<DBI-TE>/UART4-RTS/PD-EINT18, 70 PD19/LCD0-DE/LVDS1-D3N/DSI1-D3N/EINK-STH/PWM1-5/UART4-CTS/PD-EINT19, 71 PF6/PF-EINT6, 72 PF0/SDC0-D1/JTAG-MS/TRACE-DATA3/UART5-RTS/TWI2-SCK/PF-EINT0, 73 PF3/SDC0-D0/JTAG-DI/TRACE-DATA0/UART5-CTS/TWI2-SDA/PF-EINT3, 74 PF2/SDC0-CLK/UART0-TX/TRACE-CLK/PF-EINT2, 75 PF1/SDC0-CMD/JTAG-DO/TRACE-DATA2/PF-EINT1, 76 PF4/SDC0-D3/UART0-RX/UART5-RX/PF-EINT4, 77 PF5/SDC0-D2/JTAG-CK/TRACE-DATA1/UART5-TX/PF-EINT5, 78 PD20/LCD0-HSYNC/DSI-TRIG-LCD-TE1/TWI0-SCK/EINK-CKV /PCIE-CLKREQN/UART4-TX/TWI3-SCK/PWM0-2/PD-EINT20, 79 PD21/LCD0-VSYNC/TWI0-SDA/EINK-MODE/PCIE-WAKEN/UART4-RX/TWI3-SDA/PWM0-3/PD-EINT21, 80 PD22/PWM0-4/EINK-STV/PCIE-PERSTN/TWI0-SCK/TWI2-SCK/PWM1-4/PD-EINT22, 81 PD23/PWM0-5/PCIE-CLKREQN/TWI0-SDA/TWI2-SDA/PWM1-5/PD-EINT23, 82 PH15/UART5-RTS/LEDC/DSI-TRIG-LCD-TE1/RGMII0-EPHY-25/50M/PH-EINT15, 83 PH3/TWI1-SDA/I2S2-BCLK/RGMII0-CLKIN/RMII0-RXER/SPI1-MISO/PH-EINT3, 84 PH12/DMIC-DATA3/SPI2-CS1/RGMII0-RXCK/RMII0-NULL/PH-EINT12, 85 PH2/TWI1-SCK/I2S2-MCLK/RGMII0-RXCTL/RMII0-CRS-DV/SPI1-CS1/PH-EINT2, 86 PH1/TWI0-SDA/I2S2-DOUT3/I2S2-DIN3/RGMII0-RXD0/RMII0-RXD0/TWI3-SDA/SPI1-WP/PH-EINT1, 87 PH0/TWI0-SCK/I2S2-DOUT2/I2S2-DIN2/RGMII0-RXD1/RMII0-RXD1/TWI3-SCK/SPI1-HOLD/PH-EINT0, 88 PH11/DMIC-DATA2/SPI2-MISO/RGMII0-RXD2/RMII0-NULL/PH-EINT11, 89 PH10/DMIC-DATA1/SPI2-MOSI/RGMII0-RXD3/RMII0-NULL/PH-EINT10, 90 PH6/UART3-RTS/I2S2-DOUT1/I2S2-DIN0/RGMII0-TXCK/RMII0-TXCK/SPI1-CLK/PH-EINT6, 91 PH7/UART3-CTS/SPI2-CS2/DSI-TRIG-LCD-TE1/RGMII0-TXCTL/RMII0-TXEN/PH-EINT7, 92 PH5/UART3-RX/I2S2-DIN1/I2S2-DOUT0/RGMII0-TXD0/RMII0-TXD0/SPI1-MOSI/PH-EINT5, 93 PH4/UART3-TX/SPI2-CS3/I2S2-LRCK/RGMII0-TXD1/RMII0-TXD1/SPI1-CS0/PH-EINT4, 94 PH14/UART5-RX/RGMII0-TXD2/RMII0-NULL/TWI7-SCK/PH-EINT14, 95 GND, 96 PH13/UART5-TX/RGMII0-TXD3/RMII0-NULL/TWI7-SDA/PH-EINT13, 97 PH9/DMIC-DATA0/SPI2-CS0/RGMII0-MDIO/PH-EINT9, 98 PH8/DMIC-CLK/SPI2-CLK/RGMII0-MDC/PH-EINT8, 99 PH16/UART5-CTS/IR-TX/PH-EINT16, 100 PJ22/PWM1-4/UART3-TX/UART2-RTS/TWI7-SCK/TWI3-SCK/TWI11-SCK/LCD0-D8/PJ-EINT22, 101 PJ23/PWM1-5/UART3-RX/UART2-CTS/TWI7-SDA/TWI3-SDA/TWI11-SDA/LCD0-D9/PJ-EINT23, 102 PJ24/PWM1-6/UART4-TX/TWI4-SCK/SPI3-CLK/PJ-EINT24, 103 PJ25/PWM1-7/UART4-RX/TWI4-SDA/SPI3-MOSI/PJ-EINT25, 104 PJ26/PWM1-8/UART4-RTS/UART2-TX/TWI5-SCK/SPI3-MISO/LCD0-D16/PJ-EINT26, 105 PJ27/PWM1-9/UART4-CTS/UART2-RX/DSI-TRIG-LCD-TE1/TWI5-SDA/SPI3-CS0/LCD0-D17/PJ-EINT27, 106 PB0/UART2-TX/UART0-TX/SPI2-CS0/DSI-TRIG-LCD-TE1/LCD0-D0/JTAG-MS/PB-EINT0, 107 PB1/UART2-RX/UART0-RX/SPI2-CLK/LCD0-D1/JTAG-CK/PB-EINT1, 108 PB2/UART2-RTS/SPI2-MOSI/HDMI-SCL/LCD0-D8/JTAG-DO/TWI0-SCK/PB-EINT2, 109 PB3/UART2-CTS/SPI2-MISO/HDMI-SDA/LCD0-D9/JTAG-DI/TWI0-SDA/PB-EINT3, 110 PB4/PWM0-0/I2S0-MCLK/SPI2-CS1/HDMI-CEC/LCD0-D16/TRACE-CLK/TWI1-SCK/PB-EINT4, 111 PB5/I2S0-BCLK/SPI2-CS2/PWM0-1/LCD0-D17/TRACE-DATA0/TWI1-SDA/PB-EINT5, 112 PB6/CLK-FANOUT1/I2S0-LRCK/SPI2-CS3/PWM0-2/PWM0-8/TRACE-DATA1/PB-EINT6, 113 PB7/CLK-FANOUT2/I2S0-DOUT0/I2S0-DIN1/PWM0-9/OWA0-IN/TRACE-DATA2/TWI1-SCK/PB-EINT7, 114 PB8/CLK-FANOUT3/I2S0-DIN0/I2S0-DOUT1/PWM1-0/OWA0-OUT/TRACE-DATA3/TWI1-SDA/PB-EINT8, 115 PB9/UART0-TX/I2S0-DIN2/I2S0-DOUT2/PWM1-1/WATCHDOG-SIG/LCD0-D16/TWI8-SCK/TWI0-SCK/PB-EINT9, 116 PB10/UART0-RX/I2S0-DIN3/I2S0-DOUT3/PWM1-2/PLL-LOCK-DBG/LCD0-D17/TWI8-SDA/TWI0-SDA/PB-EINT10, 117 USB0-DM, 118 USB0-DP, 119 USB1-DM, 120 USB1-DP, 121 PCIE1-TX0P/USB2-U3-TX0P, 122 PCIE1-TX0N/USB2-U3-TX0N, 123 USB2-DM, 124 USB2-DP, 125 PCIE1-RX0P/USB2-U3-RX0P, 126 PCIE1-RX0N/USB2-U3-RX0N, 127 COMB1-REF-CLKP, 128 COMB1-REF-CLKN, 129 PE11/TWI4-SDA/SPI3-MISO/I2S3-DIN2/I2S3-DOUT2/PCIE-CLKREQN/NCSI0-D7/UART1-CTS/PE-EINT11, 130 PE13/SPI3-CLK/PCIE-PERSTN/UART1-RX/PE-EINT13, 131 PE14/SPI3-MOSI/PWM1-8/PCIE-CLKREQN/IR-RX/TWI9-SCK/PE-EINT14, 132 PE12/SPI3-CS0/I2S3-DOUT0/I2S3-DIN1/PCIE-WAKEN/UART1-TX/PE-EINT12, 133 PE15/SPI3-CS1/PWM1-9/IR-RX/TWI9-SDA/PE-EINT15, 134 DP-HPD, 135 DP-AUXN, 136 DP-AUXP, 137 TYPEC-TX1P/U3-TX0P/DP/EDP-TX0P, 138 TYPEC-TX1N/U3-TX0N/DP/EDP-TX0N, 139 TYPEC-RX1P/U3-RX0N/DP/EDP-TX1P, 140 TYPEC-RX1N/U3-RX0P/DP/EDP-TX1N, 141 TYPEC-RX2P/U3-RX0P/DP/EDP-TX2P, 142 TYPEC-RX2N/U3-RX0N/DP/EDP-TX2N, 143 TYPEC-TX2P/U3-TX0P/DP/EDP-TX3P, 144 TYPEC-TX2N/U3-TX0N/DP/EDP-TX3N, 145 FEL, 146 PC7/NAND-RB1/SPI0-CS1/SPIF0-DQS/PC-EINT7, 147 PC3/NAND-CE1/SPI0-CS0/SPIF0-CS0/PC-EINT3, 148 PC4/NAND-CE0/SPI0-MISO/SPIF0-MISO/PC-EINT4, 149 PC2/NAND-CLE/SPI0-MOSI/SPIF0-MOSI/PC-EINT2, 150 PC12/NAND-DQS/SPI0-CLK/SPIF0-CLK/PC-EINT12, 151 PC15/NAND-DQ1/SDC2-D2/SDC3-D2/SPI0-WP/SPIF0-WP/PC-EINT15, 152 PC16/NAND-DQ0/SDC2-D7/SDC3-D7/SPI0-HOLD/SPIF0-HOLD/PC-EINT16, 153 PC13/NAND-DQ3/SDC2-D1/SDC3-D1/PC-EINT13, 154 PC14/NAND-DQ2/SDC2-D6/SDC3-D6/PC-EINT14, 155 GPADC4, 156 GPADC5, 157 GPADC6, 158 GND, 159 PMU-IRQ, 160 PMU-SCK, 161 PMU-SDA, 162 GND, 163 5V-IN, 164 5V-IN, 165 GND, 166 BKUPBAT, 167 RESET, 168 PWRON, 169 PM5/S-UART0-RX/S-TWI2-SDA/S-TWI1-SDA/S-UART1-RX/S-PWM0-1/S-IR-RX/PM-EINT5, 170 PL13/S-UART1-RX/S-TWI1-SDA/S-TWI2-SDA/PL-EINT13, 171 PL12/S-UART1-TX/S-TWI1-SCK/S-TWI2-SCK/S-IR-RX/PL-EINT12, 172 PL2/S-UART1-TX/S-UART0-TX/S-TWI1-SDA/S-PWM0-0/PL-EINT2, 173 PL3/S-UART1-RX/S-UART0-RX/S-TWI1-SCK/S-IR-RX/S-PWM0-1/PL-EINT3, 174 PL4/S-JTAG-MS/S-TWI2-SCK/S-SPI0-CS0/S-IR-RX/S-PWM0-2/PL-EINT4, 175 PL5/S-JTAG-CK/S-TWI2-SDA/S-SPI0-CLK/S-PWM0-3/PL-EINT5, 176 PL6/S-JTAG-DO/S-UART0-TX/S-SPI0-MOSI/S-IR-RX/S-PWM0-4/PL-EINT6, 177 PL7/S-JTAG-DI/S-UART0-RX/S-SPI0-MISO/S-PWM0-5/PL-EINT7, 178 PL8/S-TWI1-SCK/S-UART1-TX/S-TWI0-SCK/S-TWI2-SCK/S-PWM0-6/PL-EINT8, 179 PL9/S-TWI1-SDA/S-UART1-RX/S-TWI0-SDA/S-TWI2-SDA/S-PWM0-7/PL-EINT9, 180 PL10/S-UART0-TX/S-TWI2-SCK/S-UART1-TX/S-PWM0-8/PL-EINT10, 181 PL11/S-UART0-RX/S-TWI2-SDA/S-UART1-RX/S-IR-RX/S-PWM0-9/PL-EINT11, 182 AVCC, 183 LRADC0, 184 PK12/MCSIB-D1N/UART6-RTS/PWM0-5/NCSI1-D7/PK-EINT12, 185 PK13/MCSIB-D1P/UART6-CTS/PWM0-6/NCSI1-D6/PK-EINT13, 186 PK10/MCSIB-D0N/UART6-TX/PWM0-3/NCSI1-D9/PK-EINT10, 187 PK11/MCSIB-D0P/UART6-RX/PWM0-4/NCSI1-D8/PK-EINT11, 188 GND, 189 COMB0-REF-CLKN, 190 COMB0-REF-CLKP

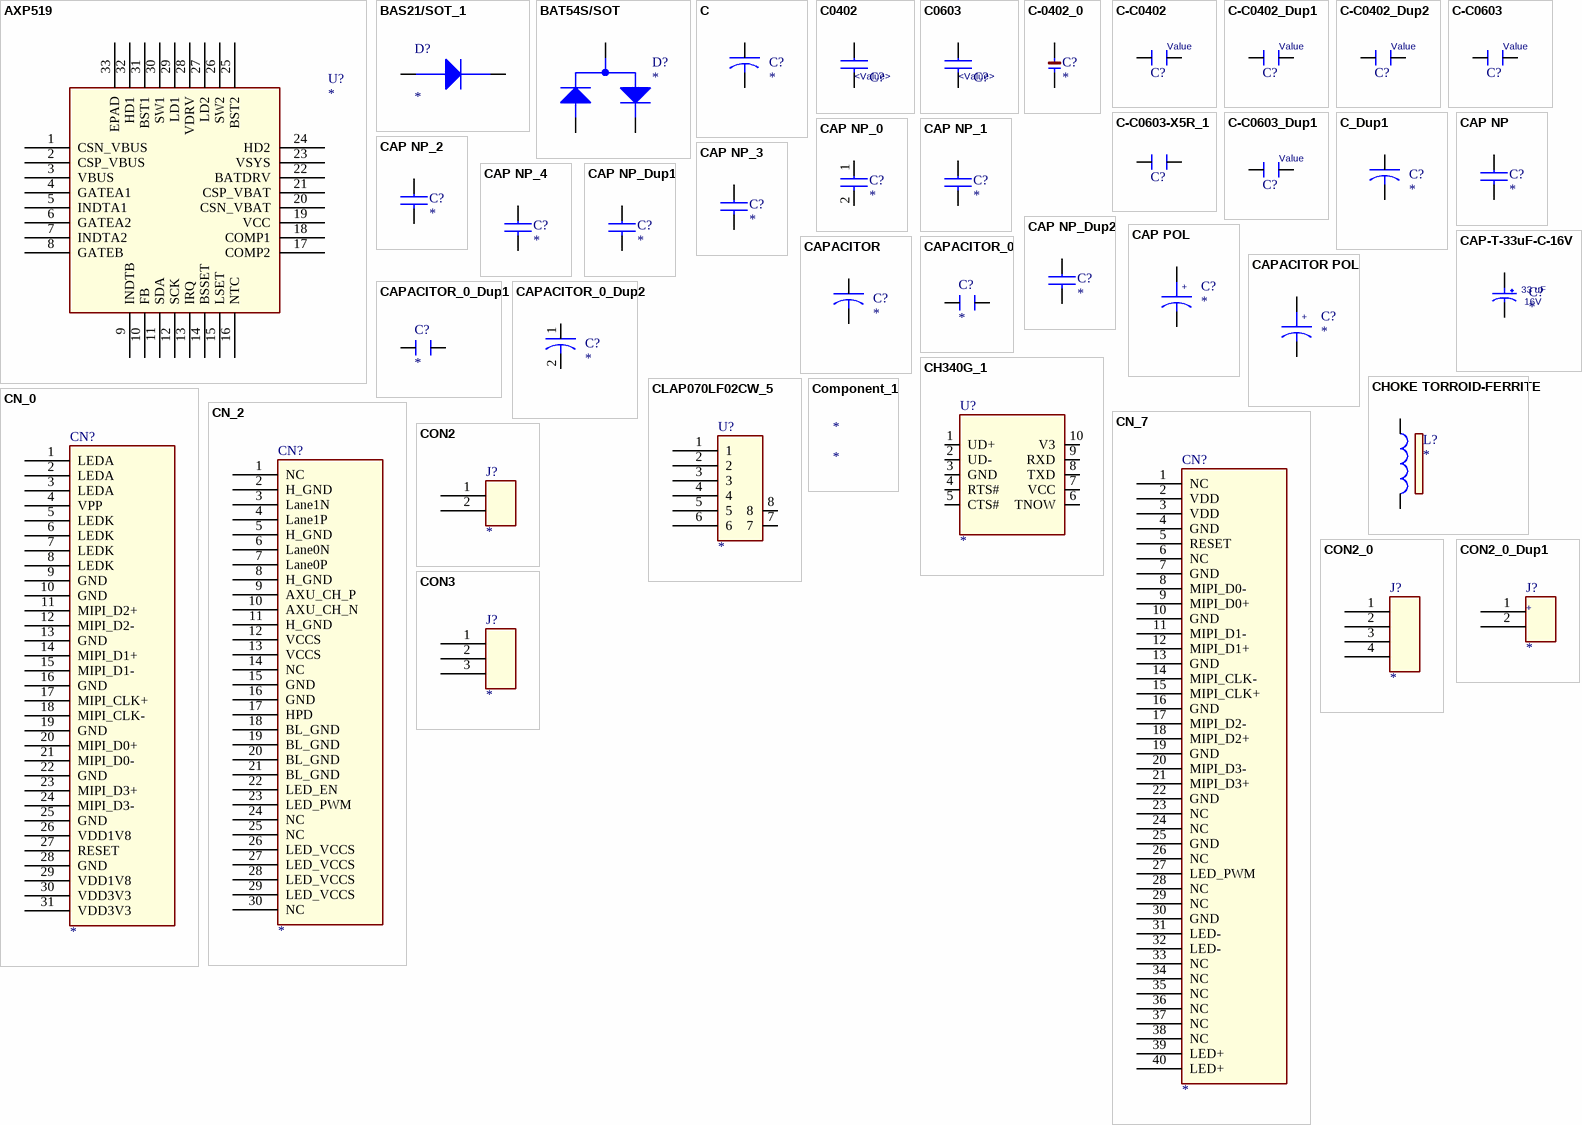
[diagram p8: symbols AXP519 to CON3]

## AXP519
designator U?
pins: 1 CSN_VBUS, 2 CSP_VBUS, 3 VBUS, 4 GATEA1, 5 INDTA1, 6 GATEA2, 7 INDTA2, 8 GATEB, 9 INDTB, 10 FB, 11 SDA, 12 SCK, 13 IRQ, 14 BSSET, 15 LSET, 16 NTC, 17 COMP2, 18 COMP1, 19 VCC, 20 CSN_VBAT, 21 CSP_VBAT, 22 BATDRV, 23 VSYS, 24 HD2, 25 BST2, 26 SW2, 27 LD2, 28 VDRV, 29 LD1, 30 SW1, 31 BST1, 32 HD1, 33 EPAD

## BAS21/SOT_1
designator D?
pins: 1 ANODE, 2 CATHODE

## BAT54S/SOT
designator D?
pins: 1, 2, 3

## C
designator C?
footprint C0402
pins: 1, 2

## C0402
designator C?, comment <Value>
footprint C0402
pins: 1, 2

## C0603
designator C?, comment <Value>
footprint C0603
pins: 1, 2

## C-0402_0
designator C?
footprint CCS-0402
pins: 1, 2

## C-C0402
designator C?, comment Value
footprint C0402
pins: 1, 2

## C-C0402_Dup1
designator C?, comment Value
footprint C0402
pins: 1, 2

## C-C0402_Dup2
designator C?, comment Value
footprint C0402
pins: 1, 2

## C-C0603
designator C?, comment Value
footprint C0603
pins: 1, 2

## C-C0603-X5R_1
designator C?, comment 10uF-10V  (value not drawn)
Parameter: C0603-X5R
footprint C0603
pins: 1, 2

## C-C0603_Dup1
designator C?, comment Value
footprint C0603
pins: 1, 2

## C_Dup1
designator C?
pins: 1, 2

## CAP NP
designator C?
pins: 1, 2

## CAP NP_0
designator C?
pins: 1, 2

## CAP NP_1
designator C?
pins: 1, 2

## CAP NP_2
designator C?
pins: 1, 2

## CAP NP_3
designator C?
pins: 1, 2

## CAP NP_4
designator C?
Part Number: VJ0603; Manufacturer #1???: FengHua(风华); Rating Voltage: 50(A)Vdc; Medium material: COG(NP0)/COH/X7R; Description #1: 介质材料[COG（NPO）/COH]通用型属I类电容，容量稳定，不随温度、时间和电压变化而变化，适用高频电路。; Description #2: X7R贴片电容属EIA规定的Class 2类材料电容，容量随温度、时间、电压变化而变化。
pins: 1, 2

## CAP NP_Dup1
designator C?
pins: 1, 2

## CAP NP_Dup2
designator C?
pins: 1, 2

## CAP POL
designator C?
pins: 1, 2

## CAP-T-33uF-C-16V
designator C?  VAL: 33 uF  TEN: 16V
REF: TPSC336K016R0150; TOL: 10%; DESIG: Tantalum Capacitor Low ESR; BOI: C; TEMP: -55癈 ?125癈; FAB: AVX; DEV: CPS_6032-28_01
pins: 1 P, 2 M

## CAPACITOR
designator C?
pins: 1, 2

## CAPACITOR POL
designator C?
pins: 1, 2

## CAPACITOR_0
designator C?
pins: 1, 2

## CAPACITOR_0_Dup1
designator C?
pins: 1, 2

## CAPACITOR_0_Dup2
designator C?
pins: 1, 2

## CH340G_1
designator U?
footprint SO16
pins: 1 UD+, 2 UD-, 3 GND (power), 4 RTS#, 5 CTS#, 6 TNOW, 7 VCC (power), 8 TXD, 9 RXD, 10 V3

## CHOKE TORROID-FERRITE
designator L?
pins: 1, 2

## CLAP070LF02CW_5
designator U?
pins: 1, 2, 3, 4, 5, 6, 7, 8

## CN_0
designator CN?
pins: 1 LEDA, 2 LEDA, 3 LEDA, 4 VPP, 5 LEDK, 6 LEDK, 7 LEDK, 8 LEDK, 9 GND, 10 GND, 11 MIPI_D2+, 12 MIPI_D2-, 13 GND, 14 MIPI_D1+, 15 MIPI_D1-, 16 GND, 17 MIPI_CLK+, 18 MIPI_CLK-, 19 GND, 20 MIPI_D0+, 21 MIPI_D0-, 22 GND, 23 MIPI_D3+, 24 MIPI_D3-, 25 GND, 26 VDD1V8, 27 RESET, 28 GND, 29 VDD1V8, 30 VDD3V3, 31 VDD3V3

## CN_2
designator CN?
pins: 1 NC, 2 H_GND, 3 Lane1N, 4 Lane1P, 5 H_GND, 6 Lane0N, 7 Lane0P, 8 H_GND, 9 AXU_CH_P, 10 AXU_CH_N, 11 H_GND, 12 VCCS, 13 VCCS, 14 NC, 15 GND, 16 GND, 17 HPD, 18 BL_GND, 19 BL_GND, 20 BL_GND, 21 BL_GND, 22 LED_EN, 23 LED_PWM, 24 NC, 25 NC, 26 LED_VCCS, 27 LED_VCCS, 28 LED_VCCS, 29 LED_VCCS, 30 NC

## CN_7
designator CN?
pins: 1 NC, 2 VDD, 3 VDD, 4 GND, 5 RESET, 6 NC, 7 GND, 8 MIPI_D0-, 9 MIPI_D0+, 10 GND, 11 MIPI_D1-, 12 MIPI_D1+, 13 GND, 14 MIPI_CLK-, 15 MIPI_CLK+, 16 GND, 17 MIPI_D2-, 18 MIPI_D2+, 19 GND, 20 MIPI_D3-, 21 MIPI_D3+, 22 GND, 23 NC, 24 NC, 25 GND, 26 NC, 27 LED_PWM, 28 NC, 29 NC, 30 GND, 31 LED-, 32 LED-, 33 NC, 34 NC, 35 NC, 36 NC, 37 NC, 38 NC, 39 LED+, 40 LED+

## Component_1
designator *

## CON2
designator J?
pins: 1, 2

## CON2_0
designator J?
pins: 1, 2, 3, 4

## CON2_0_Dup1
designator J?
pins: 1, 2

## CON3
designator J?
pins: 1, 2, 3

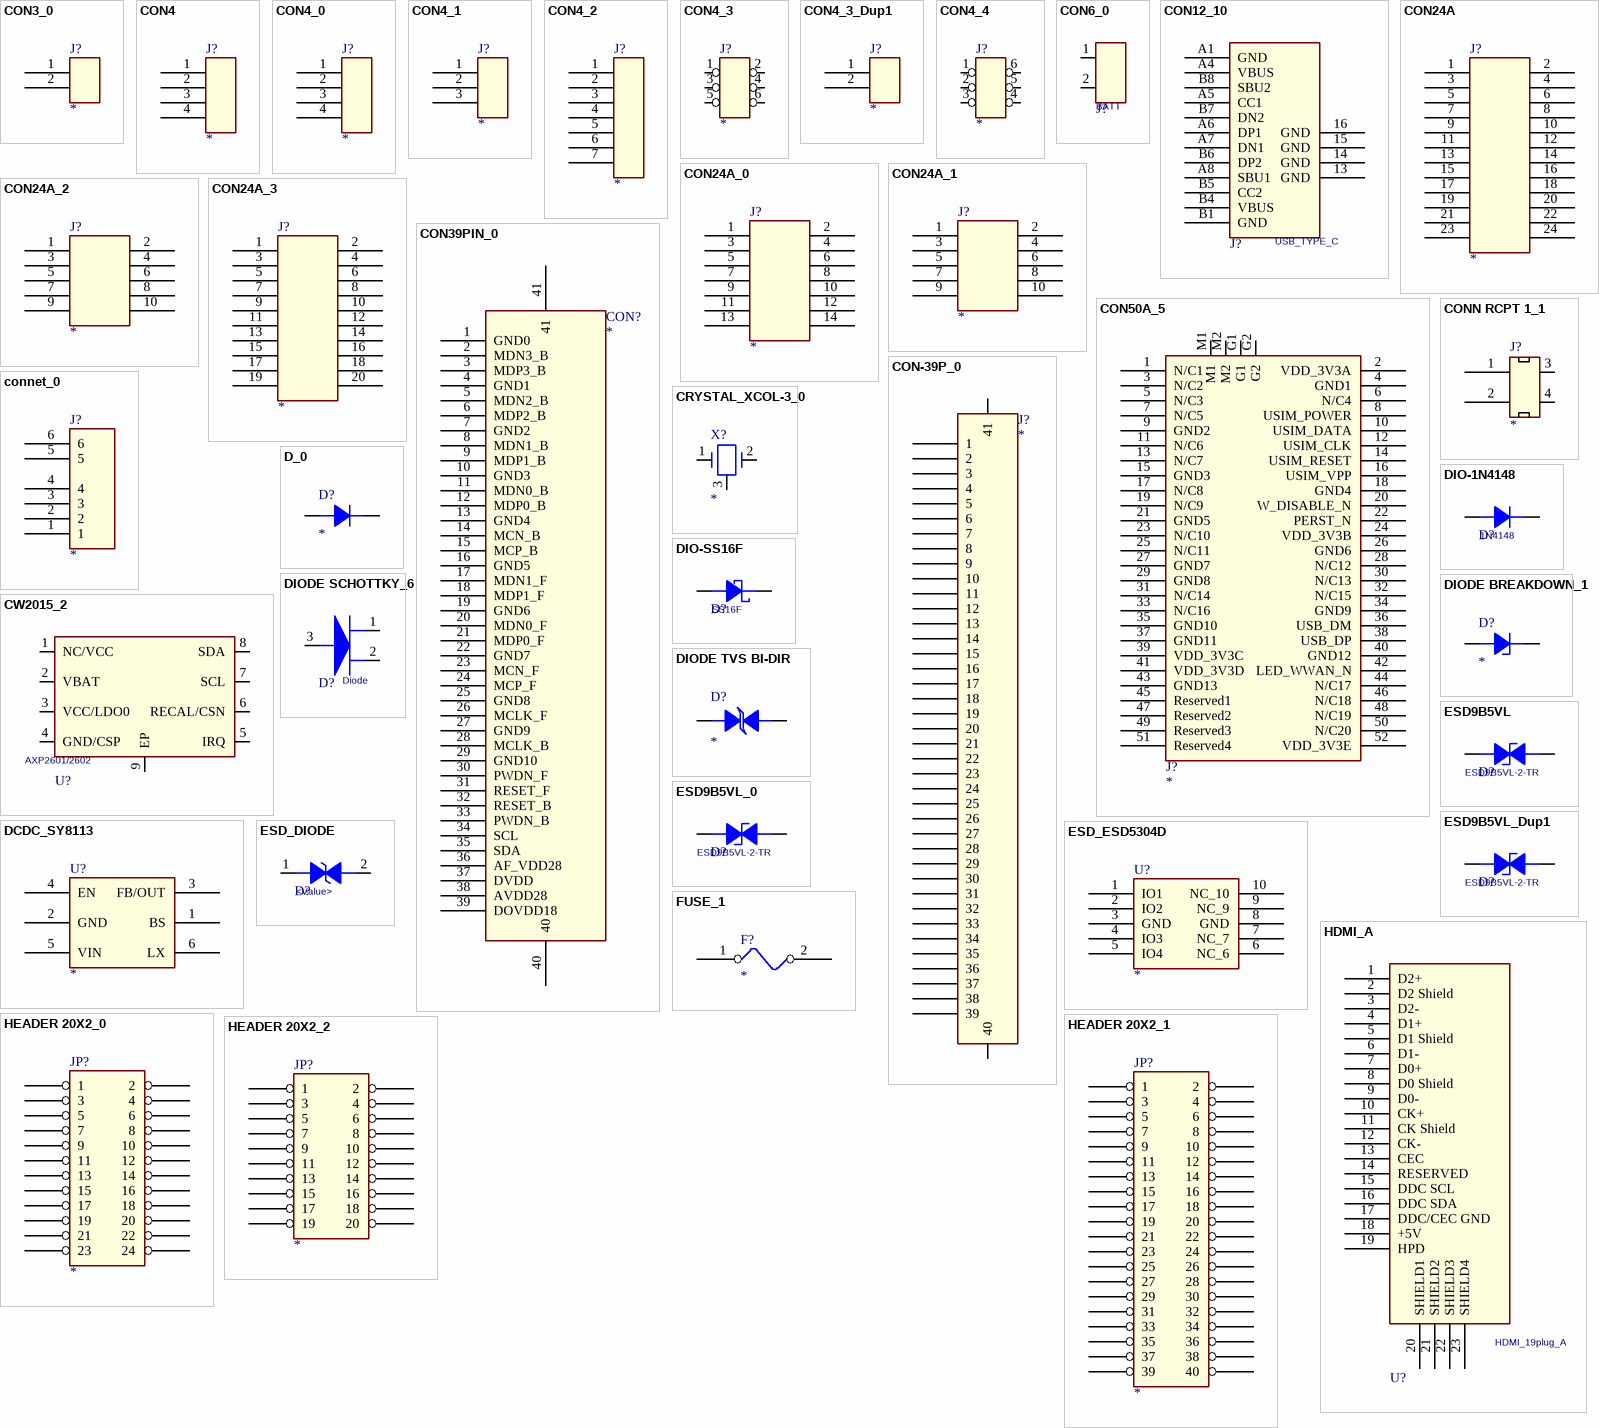
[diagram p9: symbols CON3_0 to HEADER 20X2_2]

## CON3_0
designator J?
pins: 1, 2

## CON4
designator J?
pins: 1, 2, 3, 4

## CON4_0
designator J?
pins: 1, 2, 3, 4

## CON4_1
designator J?
pins: 1, 2, 3

## CON4_2
designator J?
pins: 1, 2, 3, 4, 5, 6, 7

## CON4_3
designator J?
pins: 1, 2, 3, 4, 5, 6

## CON4_3_Dup1
designator J?
pins: 1, 2

## CON4_4
designator J?
pins: 1, 2, 3, 4, 5, 6

## CON6_0
designator J?, comment BATT
CON;HDR,6PX1,1MM,R/A,H1.9,SMT; VENDER P/N: 3800-6; VENDER: E&T; P/N: XXXXXXXXXXXX; device: CONN_ENT3800_6_1
pins: 1, 2

## CON12_10
designator J?, comment USB_TYPE_C
pins: 13 GND, 14 GND, 15 GND, 16 GND, A1 GND, A4 VBUS, A5 CC1, A6 DP1, A7 DN1, A8 SBU1, B1 GND, B4 VBUS, B5 CC2, B6 DP2, B7 DN2, B8 SBU2

## CON24A
designator J?
pins: 1, 2, 3, 4, 5, 6, 7, 8, 9, 10, 11, 12, 13, 14, 15, 16, 17, 18, 19, 20, 21, 22, 23, 24

## CON24A_0
designator J?
pins: 1, 2, 3, 4, 5, 6, 7, 8, 9, 10, 11, 12, 13, 14

## CON24A_1
designator J?
pins: 1, 2, 3, 4, 5, 6, 7, 8, 9, 10

## CON24A_2
designator J?
pins: 1, 2, 3, 4, 5, 6, 7, 8, 9, 10

## CON24A_3
designator J?
pins: 1, 2, 3, 4, 5, 6, 7, 8, 9, 10, 11, 12, 13, 14, 15, 16, 17, 18, 19, 20

## CON39PIN_0
designator CON?
pins: 1 GND0, 2 MDN3_B, 3 MDP3_B, 4 GND1, 5 MDN2_B, 6 MDP2_B, 7 GND2, 8 MDN1_B, 9 MDP1_B, 10 GND3, 11 MDN0_B, 12 MDP0_B, 13 GND4, 14 MCN_B, 15 MCP_B, 16 GND5, 17 MDN1_F, 18 MDP1_F, 19 GND6, 20 MDN0_F, 21 MDP0_F, 22 GND7, 23 MCN_F, 24 MCP_F, 25 GND8, 26 MCLK_F, 27 GND9, 28 MCLK_B, 29 GND10, 30 PWDN_F, 31 RESET_F, 32 RESET_B, 33 PWDN_B, 34 SCL, 35 SDA, 36 AF_VDD28, 37 DVDD, 38 AVDD28, 39 DOVDD18, 40, 41

## CON50A_5
designator J?
pins: 1 N/C1, 2 VDD_3V3A, 3 N/C2, 4 GND1, 5 N/C3, 6 N/C4, 7 N/C5, 8 USIM_POWER, 9 GND2, 10 USIM_DATA, 11 N/C6, 12 USIM_CLK, 13 N/C7, 14 USIM_RESET, 15 GND3, 16 USIM_VPP, 17 N/C8, 18 GND4, 19 N/C9, 20 W_DISABLE_N, 21 GND5, 22 PERST_N, 23 N/C10, 24 VDD_3V3B, 25 N/C11, 26 GND6, 27 GND7, 28 N/C12, 29 GND8, 30 N/C13, 31 N/C14, 32 N/C15, 33 N/C16, 34 GND9, 35 GND10, 36 USB_DM, 37 GND11, 38 USB_DP, 39 VDD_3V3C, 40 GND12, 41 VDD_3V3D, 42 LED_WWAN_N, 43 GND13, 44 N/C17, 45 Reserved1, 46 N/C18, 47 Reserved2, 48 N/C19, 49 Reserved3, 50 N/C20, 51 Reserved4, 52 VDD_3V3E, G1, G2, M1, M2

## CON-39P_0
designator J?
footprint CON-39P
pins: 1, 2, 3, 4, 5, 6, 7, 8, 9, 10, 11, 12, 13, 14, 15, 16, 17, 18, 19, 20, 21, 22, 23, 24, 25, 26, 27, 28, 29, 30, 31, 32, 33, 34, 35, 36, 37, 38, 39, 40, 41

## CONN RCPT 1_1
designator J?
pins: 1, 2, 3, 4

## connet_0
designator J?
pins: 1, 2, 3, 4, 5, 6

## CRYSTAL_XCOL-3_0
designator X?
footprint XCOL-3
pins: 1, 2, 3 Shield (power)

## CW2015_2
designator U?, comment AXP2601/2602
pins: 1 NC/VCC, 2 VBAT, 3 VCC/LDO0, 4 GND/CSP, 5 IRQ, 6 RECAL/CSN, 7 SCL, 8 SDA, 9 EP

## D_0
designator D?
pins: 1, 2

## DCDC_SY8113
designator U?
pins: 1 BS, 2 GND, 3 FB/OUT, 4 EN, 5 VIN, 6 LX

## DIO-1N4148
designator D?, comment 1N4148
ID: DE-S0014; Parameter: LL34，0.3A
footprint SOD130_264H140
pins: 1, 2

## DIO-SS16F
designator D?, comment SS16F
ID: DE-S0003; Parameter: SMAF
footprint SOD250_380H100
pins: 1, 2

## DIODE BREAKDOWN_1
designator D?
pins: 1 ANODE, 2 CATHODE

## DIODE SCHOTTKY_6
designator D?, comment Diode
footprint SOD123
pins: 1, 2, 3

## DIODE TVS BI-DIR
designator D?
pins: 1, 2

## ESD9B5VL
designator D?, comment ESD9B5VL-2-TR
Parameter: ESD0402; ID: DE-E0001
footprint ESD0402
pins: 1 ANODE, 2 CATHODE

## ESD9B5VL_0
designator D?, comment ESD9B5VL-2-TR
Parameter: ESD0402，3PF; ID: DE-E0001
footprint ESD0402
pins: 1 ANODE, 2 CATHODE

## ESD9B5VL_Dup1
designator D?, comment ESD9B5VL-2-TR
Parameter: ESD0402; ID: DE-E0001
footprint ESD0402
pins: 1 ANODE, 2 CATHODE

## ESD_DIODE
designator D?, comment <Value>
TVS diode;DC Working Voltage(VDC):16.0V;Clamping Voltage(VCL)Ipeak = 1A,8/20s:290V Maximum;Capacitance(C)@1MHz, 1V:2pF Typical;3pF Maximum; Part Name: CDS2C16GTH; Brand: EPCOS稲炊吹
footprint R0402
pins: 1 ANODE, 2 CATHODE

## ESD_ESD5304D
designator U?
pins: 1 IO1, 2 IO2, 3 GND (power), 4 IO3, 5 IO4, 6 NC_6, 7 NC_7, 8 GND (power), 9 NC_9, 10 NC_10

## FUSE_1
designator F?
pins: 1, 2

## HDMI_A
designator U?, comment HDMI_19plug_A
pins: 1 D2+, 2 D2 Shield, 3 D2-, 4 D1+, 5 D1 Shield, 6 D1-, 7 D0+, 8 D0 Shield, 9 D0-, 10 CK+, 11 CK Shield, 12 CK-, 13 CEC, 14 RESERVED, 15 DDC SCL, 16 DDC SDA, 17 DDC/CEC GND, 18 +5V, 19 HPD, 20 SHIELD1, 21 SHIELD2, 22 SHIELD3, 23 SHIELD4

## HEADER 20X2_0
designator JP?
pins: 1, 2, 3, 4, 5, 6, 7, 8, 9, 10, 11, 12, 13, 14, 15, 16, 17, 18, 19, 20, 21, 22, 23, 24

## HEADER 20X2_1
designator JP?
pins: 1, 2, 3, 4, 5, 6, 7, 8, 9, 10, 11, 12, 13, 14, 15, 16, 17, 18, 19, 20, 21, 22, 23, 24, 25, 26, 27, 28, 29, 30, 31, 32, 33, 34, 35, 36, 37, 38, 39, 40

## HEADER 20X2_2
designator JP?
pins: 1, 2, 3, 4, 5, 6, 7, 8, 9, 10, 11, 12, 13, 14, 15, 16, 17, 18, 19, 20

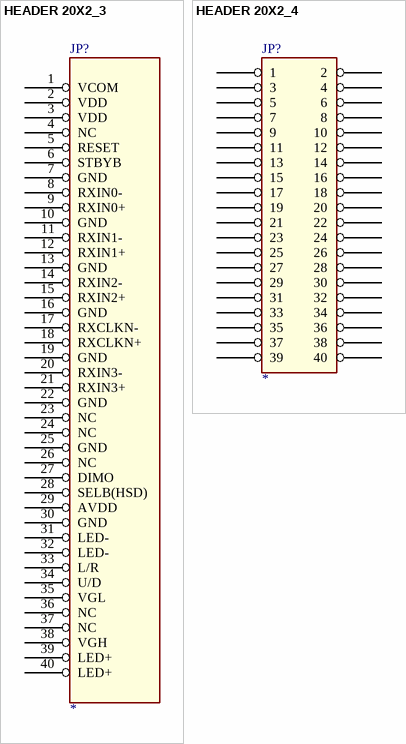
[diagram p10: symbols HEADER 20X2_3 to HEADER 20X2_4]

## HEADER 20X2_3
designator JP?
pins: 1 VCOM, 2 VDD, 3 VDD, 4 NC, 5 RESET, 6 STBYB, 7 GND, 8 RXIN0-, 9 RXIN0+, 10 GND, 11 RXIN1-, 12 RXIN1+, 13 GND, 14 RXIN2-, 15 RXIN2+, 16 GND, 17 RXCLKN-, 18 RXCLKN+, 19 GND, 20 RXIN3-, 21 RXIN3+, 22 GND, 23 NC, 24 NC, 25 GND, 26 NC, 27 DIMO, 28 SELB(HSD), 29 AVDD, 30 GND, 31 LED-, 32 LED-, 33 L/R, 34 U/D, 35 VGL, 36 NC, 37 NC, 38 VGH, 39 LED+, 40 LED+

## HEADER 20X2_4
designator JP?
pins: 1, 2, 3, 4, 5, 6, 7, 8, 9, 10, 11, 12, 13, 14, 15, 16, 17, 18, 19, 20, 21, 22, 23, 24, 25, 26, 27, 28, 29, 30, 31, 32, 33, 34, 35, 36, 37, 38, 39, 40

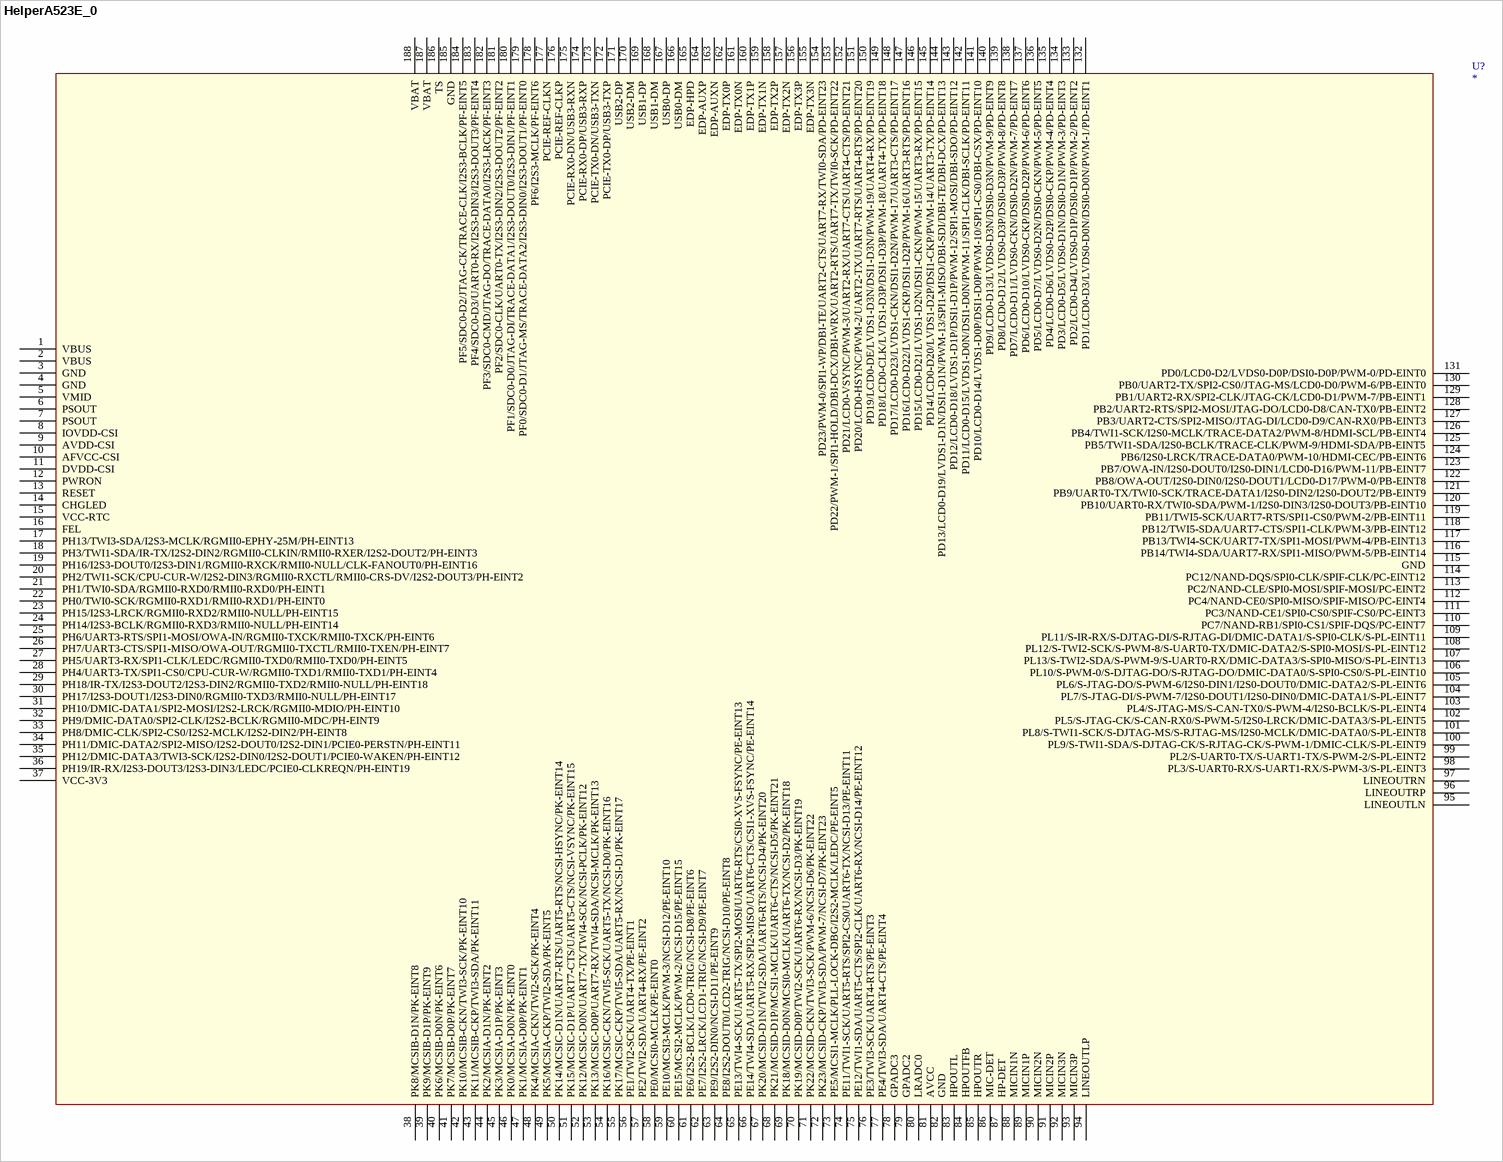
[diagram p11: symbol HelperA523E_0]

## HelperA523E_0
designator U?
pins: 1 VBUS, 2 VBUS, 3 GND, 4 GND, 5 VMID, 6 PSOUT, 7 PSOUT, 8 IOVDD-CSI, 9 AVDD-CSI, 10 AFVCC-CSI, 11 DVDD-CSI, 12 PWRON, 13 RESET, 14 CHGLED, 15 VCC-RTC, 16 FEL, 17 PH13/TWI3-SDA/I2S3-MCLK/RGMII0-EPHY-25M/PH-EINT13, 18 PH3/TWI1-SDA/IR-TX/I2S2-DIN2/RGMII0-CLKIN/RMII0-RXER/I2S2-DOUT2/PH-EINT3, 19 PH16/I2S3-DOUT0/I2S3-DIN1/RGMII0-RXCK/RMII0-NULL/CLK-FANOUT0/PH-EINT16, 20 PH2/TWI1-SCK/CPU-CUR-W/I2S2-DIN3/RGMII0-RXCTL/RMII0-CRS-DV/I2S2-DOUT3/PH-EINT2, 21 PH1/TWI0-SDA/RGMII0-RXD0/RMII0-RXD0/PH-EINT1, 22 PH0/TWI0-SCK/RGMII0-RXD1/RMII0-RXD1/PH-EINT0, 23 PH15/I2S3-LRCK/RGMII0-RXD2/RMII0-NULL/PH-EINT15, 24 PH14/I2S3-BCLK/RGMII0-RXD3/RMII0-NULL/PH-EINT14, 25 PH6/UART3-RTS/SPI1-MOSI/OWA-IN/RGMII0-TXCK/RMII0-TXCK/PH-EINT6, 26 PH7/UART3-CTS/SPI1-MISO/OWA-OUT/RGMII0-TXCTL/RMII0-TXEN/PH-EINT7, 27 PH5/UART3-RX/SPI1-CLK/LEDC/RGMII0-TXD0/RMII0-TXD0/PH-EINT5, 28 PH4/UART3-TX/SPI1-CS0/CPU-CUR-W/RGMII0-TXD1/RMII0-TXD1/PH-EINT4, 29 PH18/IR-TX/I2S3-DOUT2/I2S3-DIN2/RGMII0-TXD2/RMII0-NULL/PH-EINT18, 30 PH17/I2S3-DOUT1/I2S3-DIN0/RGMII0-TXD3/RMII0-NULL/PH-EINT17, 31 PH10/DMIC-DATA1/SPI2-MOSI/I2S2-LRCK/RGMII0-MDIO/PH-EINT10, 32 PH9/DMIC-DATA0/SPI2-CLK/I2S2-BCLK/RGMII0-MDC/PH-EINT9, 33 PH8/DMIC-CLK/SPI2-CS0/I2S2-MCLK/I2S2-DIN2/PH-EINT8, 34 PH11/DMIC-DATA2/SPI2-MISO/I2S2-DOUT0/I2S2-DIN1/PCIE0-PERSTN/PH-EINT11, 35 PH12/DMIC-DATA3/TWI3-SCK/I2S2-DIN0/I2S2-DOUT1/PCIE0-WAKEN/PH-EINT12, 36 PH19/IR-RX/I2S3-DOUT3/I2S3-DIN3/LEDC/PCIE0-CLKREQN/PH-EINT19, 37 VCC-3V3, 38 PK8/MCSIB-D1N/PK-EINT8, 39 PK9/MCSIB-D1P/PK-EINT9, 40 PK6/MCSIB-D0N/PK-EINT6, 41 PK7/MCSIB-D0P/PK-EINT7, 42 PK10/MCSIB-CKN/TWI3-SCK/PK-EINT10, 43 PK11/MCSIB-CKP/TWI3-SDA/PK-EINT11, 44 PK2/MCSIA-D1N/PK-EINT2, 45 PK3/MCSIA-D1P/PK-EINT3, 46 PK0/MCSIA-D0N/PK-EINT0, 47 PK1/MCSIA-D0P/PK-EINT1, 48 PK4/MCSIA-CKN/TWI2-SCK/PK-EINT4, 49 PK5/MCSIA-CKP/TWI2-SDA/PK-EINT5, 50 PK14/MCSIC-D1N/UART7-RTS/UART5-RTS/NCSI-HSYNC/PK-EINT14, 51 PK15/MCSIC-D1P/UART7-CTS/UART5-CTS/NCSI-VSYNC/PK-EINT15, 52 PK12/MCSIC-D0N/UART7-TX/TWI4-SCK/NCSI-PCLK/PK-EINT12, 53 PK13/MCSIC-D0P/UART7-RX/TWI4-SDA/NCSI-MCLK/PK-EINT13, 54 PK16/MCSIC-CKN/TWI5-SCK/UART5-TX/NCSI-D0/PK-EINT16, 55 PK17/MCSIC-CKP/TWI5-SDA/UART5-RX/NCSI-D1/PK-EINT17, 56 PE1/TWI2-SCK/UART4-TX/PE-EINT1, 57 PE2/TWI2-SDA/UART4-RX/PE-EINT2, 58 PE0/MCSI0-MCLK/PE-EINT0, 59 PE10/MCSI3-MCLK/PWM-3/NCSI-D12/PE-EINT10, 60 PE15/MCSI2-MCLK/PWM-2/NCSI-D15/PE-EINT15, 61 PE6/I2S2-BCLK/LCD0-TRIG/NCSI-D8/PE-EINT6, 62 PE7/I2S2-LRCK/LCD1-TRIG/NCSI-D9/PE-EINT7, 63 PE9/I2S2-DIN0/NCSI-D11/PE-EINT9, 64 PE8/I2S2-DOUT0/LCD2-TRIG/NCSI-D10/PE-EINT8, 65 PE13/TWI4-SCK/UART5-TX/SPI2-MOSI/UART6-RTS/CSI0-XVS-FSYNC/PE-EINT13, 66 PE14/TWI4-SDA/UART5-RX/SPI2-MISO/UART6-CTS/CSI1-XVS-FSYNC/PE-EINT14, 67 PK20/MCSID-D1N/TWI2-SDA/UART6-RTS/NCSI-D4/PK-EINT20, 68 PK21/MCSID-D1P/MCSI1-MCLK/UART6-CTS/NCSI-D5/PK-EINT21, 69 PK18/MCSID-D0N/MCSI0-MCLK/UART6-TX/NCSI-D2/PK-EINT18, 70 PK19/MCSID-D0P/TWI2-SCK/UART6-RX/NCSI-D3/PK-EINT19, 71 PK22/MCSID-CKN/TWI3-SCK/PWM-6/NCSI-D6/PK-EINT22, 72 PK23/MCSID-CKP/TWI3-SDA/PWM-7/NCSI-D7/PK-EINT23, 73 PE5/MCSI1-MCLK/PLL-LOCK-DBG/I2S2-MCLK/LEDC/PE-EINT5, 74 PE11/TWI1-SCK/UART5-RTS/SPI2-CS0/UART6-TX/NCSI-D13/PE-EINT11, 75 PE12/TWI1-SDA/UART5-CTS/SPI2-CLK/UART6-RX/NCSI-D14/PE-EINT12, 76 PE3/TWI3-SCK/UART4-RTS/PE-EINT3, 77 PE4/TWI3-SDA/UART4-CTS/PE-EINT4, 78 GPADC3, 79 GPADC2, 80 LRADC0, 81 AVCC, 82 GND, 83 HPOUTL, 84 HPOUTFB, 85 HPOUTR, 86 MIC-DET, 87 HP-DET, 88 MICIN1N, 89 MICIN1P, 90 MICIN2N, 91 MICIN2P, 92 MICIN3N, 93 MICIN3P, 94 LINEOUTLP, 95 LINEOUTLN, 96 LINEOUTRP, 97 LINEOUTRN, 98 PL3/S-UART0-RX/S-UART1-RX/S-PWM-3/S-PL-EINT3, 99 PL2/S-UART0-TX/S-UART1-TX/S-PWM-2/S-PL-EINT2, 100 PL9/S-TWI1-SDA/S-DJTAG-CK/S-RJTAG-CK/S-PWM-1/DMIC-CLK/S-PL-EINT9, 101 PL8/S-TWI1-SCK/S-DJTAG-MS/S-RJTAG-MS/I2S0-MCLK/DMIC-DATA0/S-PL-EINT8, 102 PL5/S-JTAG-CK/S-CAN-RX0/S-PWM-5/I2S0-LRCK/DMIC-DATA3/S-PL-EINT5, 103 PL4/S-JTAG-MS/S-CAN-TX0/S-PWM-4/I2S0-BCLK/S-PL-EINT4, 104 PL7/S-JTAG-DI/S-PWM-7/I2S0-DOUT1/I2S0-DIN0/DMIC-DATA1/S-PL-EINT7, 105 PL6/S-JTAG-DO/S-PWM-6/I2S0-DIN1/I2S0-DOUT0/DMIC-DATA2/S-PL-EINT6, 106 PL10/S-PWM-0/S-DJTAG-DO/S-RJTAG-DO/DMIC-DATA0/S-SPI0-CS0/S-PL-EINT10, 107 PL13/S-TWI2-SDA/S-PWM-9/S-UART0-RX/DMIC-DATA3/S-SPI0-MISO/S-PL-EINT13, 108 PL12/S-TWI2-SCK/S-PWM-8/S-UART0-TX/DMIC-DATA2/S-SPI0-MOSI/S-PL-EINT12, 109 PL11/S-IR-RX/S-DJTAG-DI/S-RJTAG-DI/DMIC-DATA1/S-SPI0-CLK/S-PL-EINT11, 110 PC7/NAND-RB1/SPI0-CS1/SPIF-DQS/PC-EINT7, 111 PC3/NAND-CE1/SPI0-CS0/SPIF-CS0/PC-EINT3, 112 PC4/NAND-CE0/SPI0-MISO/SPIF-MISO/PC-EINT4, 113 PC2/NAND-CLE/SPI0-MOSI/SPIF-MOSI/PC-EINT2, 114 PC12/NAND-DQS/SPI0-CLK/SPIF-CLK/PC-EINT12, 115 GND, 116 PB14/TWI4-SDA/UART7-RX/SPI1-MISO/PWM-5/PB-EINT14, 117 PB13/TWI4-SCK/UART7-TX/SPI1-MOSI/PWM-4/PB-EINT13, 118 PB12/TWI5-SDA/UART7-CTS/SPI1-CLK/PWM-3/PB-EINT12, 119 PB11/TWI5-SCK/UART7-RTS/SPI1-CS0/PWM-2/PB-EINT11, 120 PB10/UART0-RX/TWI0-SDA/PWM-1/I2S0-DIN3/I2S0-DOUT3/PB-EINT10, 121 PB9/UART0-TX/TWI0-SCK/TRACE-DATA1/I2S0-DIN2/I2S0-DOUT2/PB-EINT9, 122 PB8/OWA-OUT/I2S0-DIN0/I2S0-DOUT1/LCD0-D17/PWM-0/PB-EINT8, 123 PB7/OWA-IN/I2S0-DOUT0/I2S0-DIN1/LCD0-D16/PWM-11/PB-EINT7, 124 PB6/I2S0-LRCK/TRACE-DATA0/PWM-10/HDMI-CEC/PB-EINT6, 125 PB5/TWI1-SDA/I2S0-BCLK/TRACE-CLK/PWM-9/HDMI-SDA/PB-EINT5, 126 PB4/TWI1-SCK/I2S0-MCLK/TRACE-DATA2/PWM-8/HDMI-SCL/PB-EINT4, 127 PB3/UART2-CTS/SPI2-MISO/JTAG-DI/LCD0-D9/CAN-RX0/PB-EINT3, 128 PB2/UART2-RTS/SPI2-MOSI/JTAG-DO/LCD0-D8/CAN-TX0/PB-EINT2, 129 PB1/UART2-RX/SPI2-CLK/JTAG-CK/LCD0-D1/PWM-7/PB-EINT1, 130 PB0/UART2-TX/SPI2-CS0/JTAG-MS/LCD0-D0/PWM-6/PB-EINT0, 131 PD0/LCD0-D2/LVDS0-D0P/DSI0-D0P/PWM-0/PD-EINT0, 132 PD1/LCD0-D3/LVDS0-D0N/DSI0-D0N/PWM-1/PD-EINT1, 133 PD2/LCD0-D4/LVDS0-D1P/DSI0-D1P/PWM-2/PD-EINT2, 134 PD3/LCD0-D5/LVDS0-D1N/DSI0-D1N/PWM-3/PD-EINT3, 135 PD4/LCD0-D6/LVDS0-D2P/DSI0-CKP/PWM-4/PD-EINT4, 136 PD5/LCD0-D7/LVDS0-D2N/DSI0-CKN/PWM-5/PD-EINT5, 137 PD6/LCD0-D10/LVDS0-CKP/DSI0-D2P/PWM-6/PD-EINT6, 138 PD7/LCD0-D11/LVDS0-CKN/DSI0-D2N/PWM-7/PD-EINT7, 139 PD8/LCD0-D12/LVDS0-D3P/DSI0-D3P/PWM-8/PD-EINT8, 140 PD9/LCD0-D13/LVDS0-D3N/DSI0-D3N/PWM-9/PD-EINT9, 141 PD10/LCD0-D14/LVDS1-D0P/DSI1-D0P/PWM-10/SPI1-CS0/DBI-CSX/PD-EINT10, 142 PD11/LCD0-D15/LVDS1-D0N/DSI1-D0N/PWM-11/SPI1-CLK/DBI-SCLK/PD-EINT11, 143 PD12/LCD0-D18/LVDS1-D1P/DSI1-D1P/PWM-12/SPI1-MOSI/DBI-SDO/PD-EINT12, 144 PD13/LCD0-D19/LVDS1-D1N/DSI1-D1N/PWM-13/SPI1-MISO/DBI-SDI/DBI-TE/DBI-DCX/PD-EINT13, 145 PD14/LCD0-D20/LVDS1-D2P/DSI1-CKP/PWM-14/UART3-TX/PD-EINT14, 146 PD15/LCD0-D21/LVDS1-D2N/DSI1-CKN/PWM-15/UART3-RX/PD-EINT15, 147 PD16/LCD0-D22/LVDS1-CKP/DSI1-D2P/PWM-16/UART3-RTS/PD-EINT16, 148 PD17/LCD0-D23/LVDS1-CKN/DSI1-D2N/PWM-17/UART3-CTS/PD-EINT17, 149 PD18/LCD0-CLK/LVDS1-D3P/DSI1-D3P/PWM-18/UART4-TX/PD-EINT18, 150 PD19/LCD0-DE/LVDS1-D3N/DSI1-D3N/PWM-19/UART4-RX/PD-EINT19, 151 PD20/LCD0-HSYNC/PWM-2/UART2-TX/UART7-RTS/UART4-RTS/PD-EINT20, 152 PD21/LCD0-VSYNC/PWM-3/UART2-RX/UART7-CTS/UART4-CTS/PD-EINT21, 153 PD22/PWM-1/SPI1-HOLD/DBI-DCX/DBI-WRX/UART2-RTS/UART7-TX/TWI0-SCK/PD-EINT22, 154 PD23/PWM-0/SPI1-WP/DBI-TE/UART2-CTS/UART7-RX/TWI0-SDA/PD-EINT23, 155 EDP-TX3N, 156 EDP-TX3P, 157 EDP-TX2N, 158 EDP-TX2P, 159 EDP-TX1N, 160 EDP-TX1P, 161 EDP-TX0N, 162 EDP-TX0P, 163 EDP-AUXN, 164 EDP-AUXP, 165 EDP-HPD, 166 USB0-DM, 167 USB0-DP, 168 USB1-DM, 169 USB1-DP, 170 USB2-DM, 171 USB2-DP, 172 PCIE-TX0-DP/USB3-TXP, 173 PCIE-TX0-DN/USB3-TXN, 174 PCIE-RX0-DP/USB3-RXP, 175 PCIE-RX0-DN/USB3-RXN, 176 PCIE-REF-CLKP, 177 PCIE-REF-CLKN, 178 PF6/I2S3-MCLK/PF-EINT6, 179 PF0/SDC0-D1/JTAG-MS/TRACE-DATA2/I2S3-DIN0/I2S3-DOUT1/PF-EINT0, 180 PF1/SDC0-D0/JTAG-DI/TRACE-DATA1/I2S3-DOUT0/I2S3-DIN1/PF-EINT1, 181 PF2/SDC0-CLK/UART0-TX/I2S3-DIN2/I2S3-DOUT2/PF-EINT2, 182 PF3/SDC0-CMD/JTAG-DO/TRACE-DATA0/I2S3-LRCK/PF-EINT3, 183 PF4/SDC0-D3/UART0-RX/I2S3-DIN3/I2S3-DOUT3/PF-EINT4, 184 PF5/SDC0-D2/JTAG-CK/TRACE-CLK/I2S3-BCLK/PF-EINT5, 185 GND, 186 TS, 187 VBAT, 188 VBAT

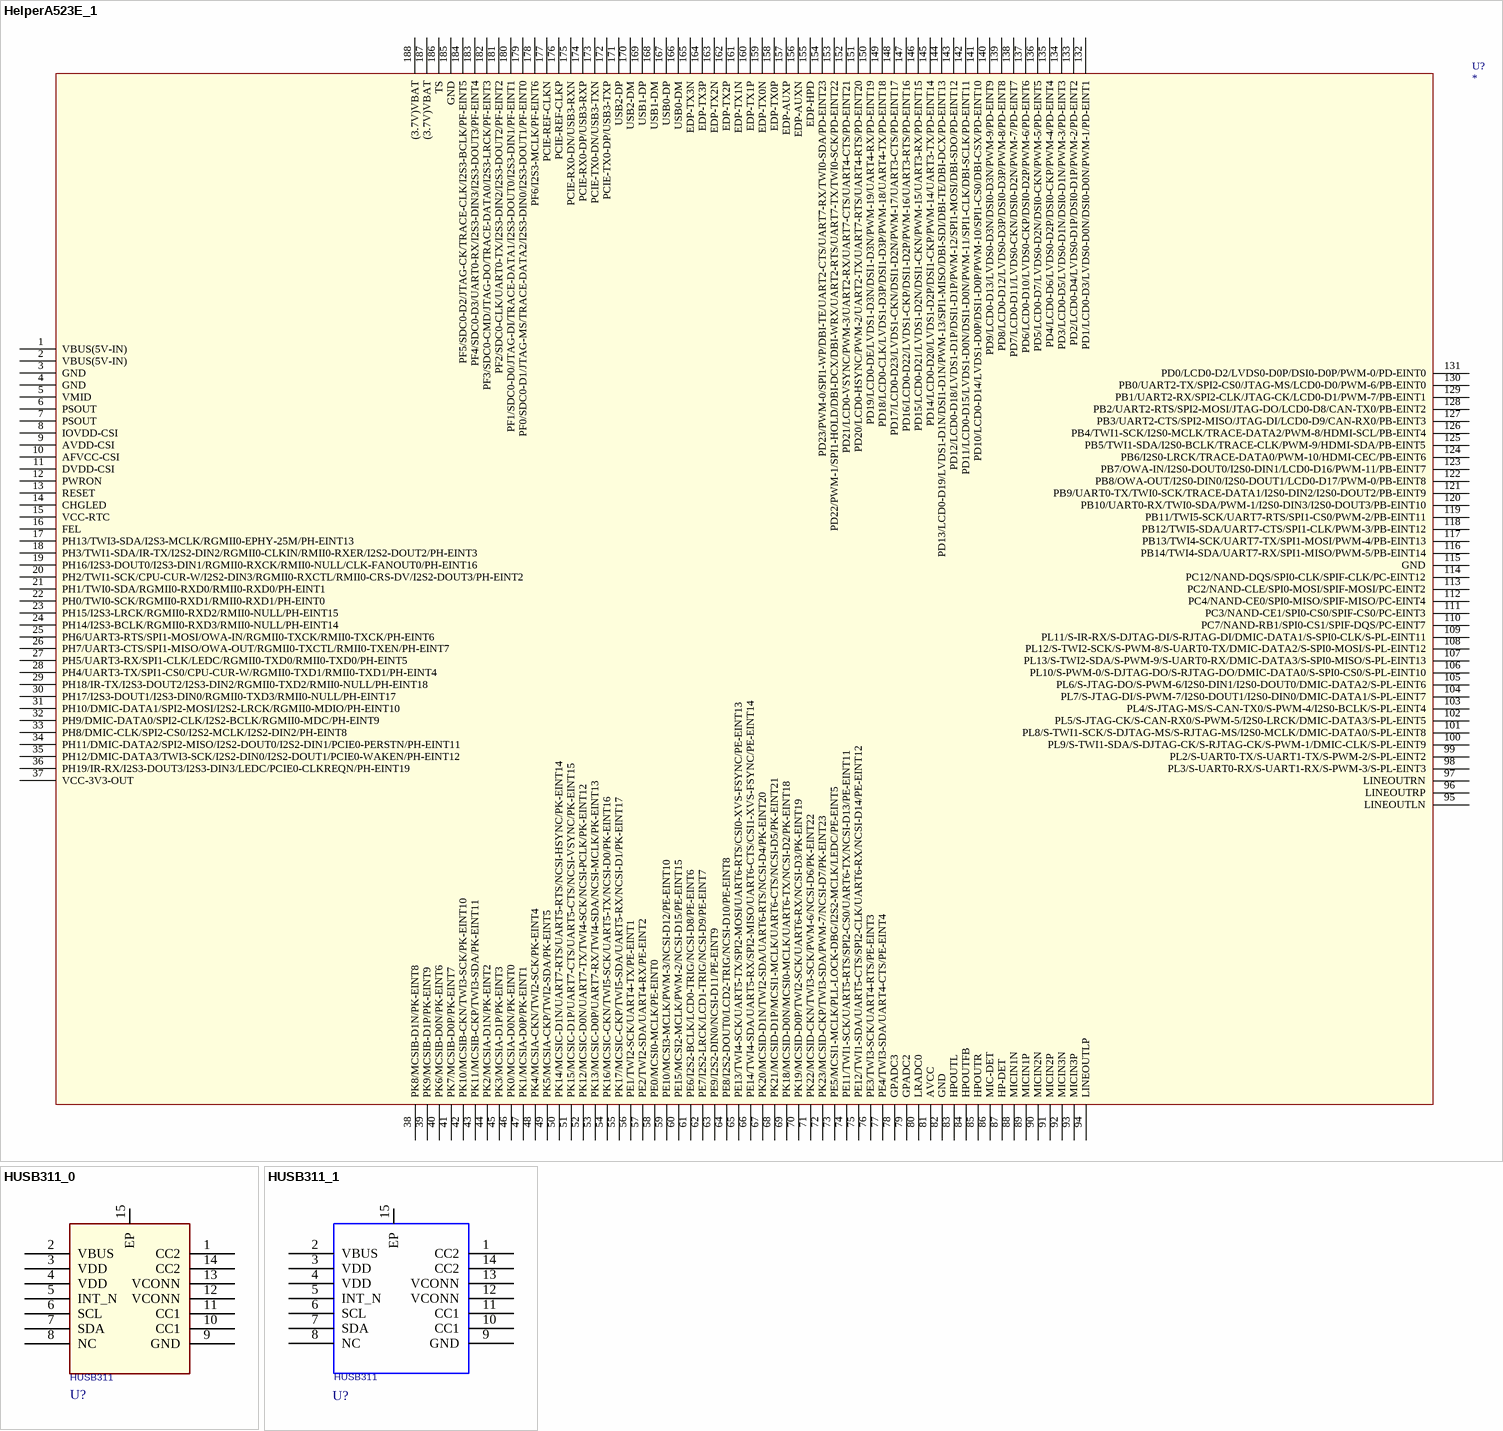
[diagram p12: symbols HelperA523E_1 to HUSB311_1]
